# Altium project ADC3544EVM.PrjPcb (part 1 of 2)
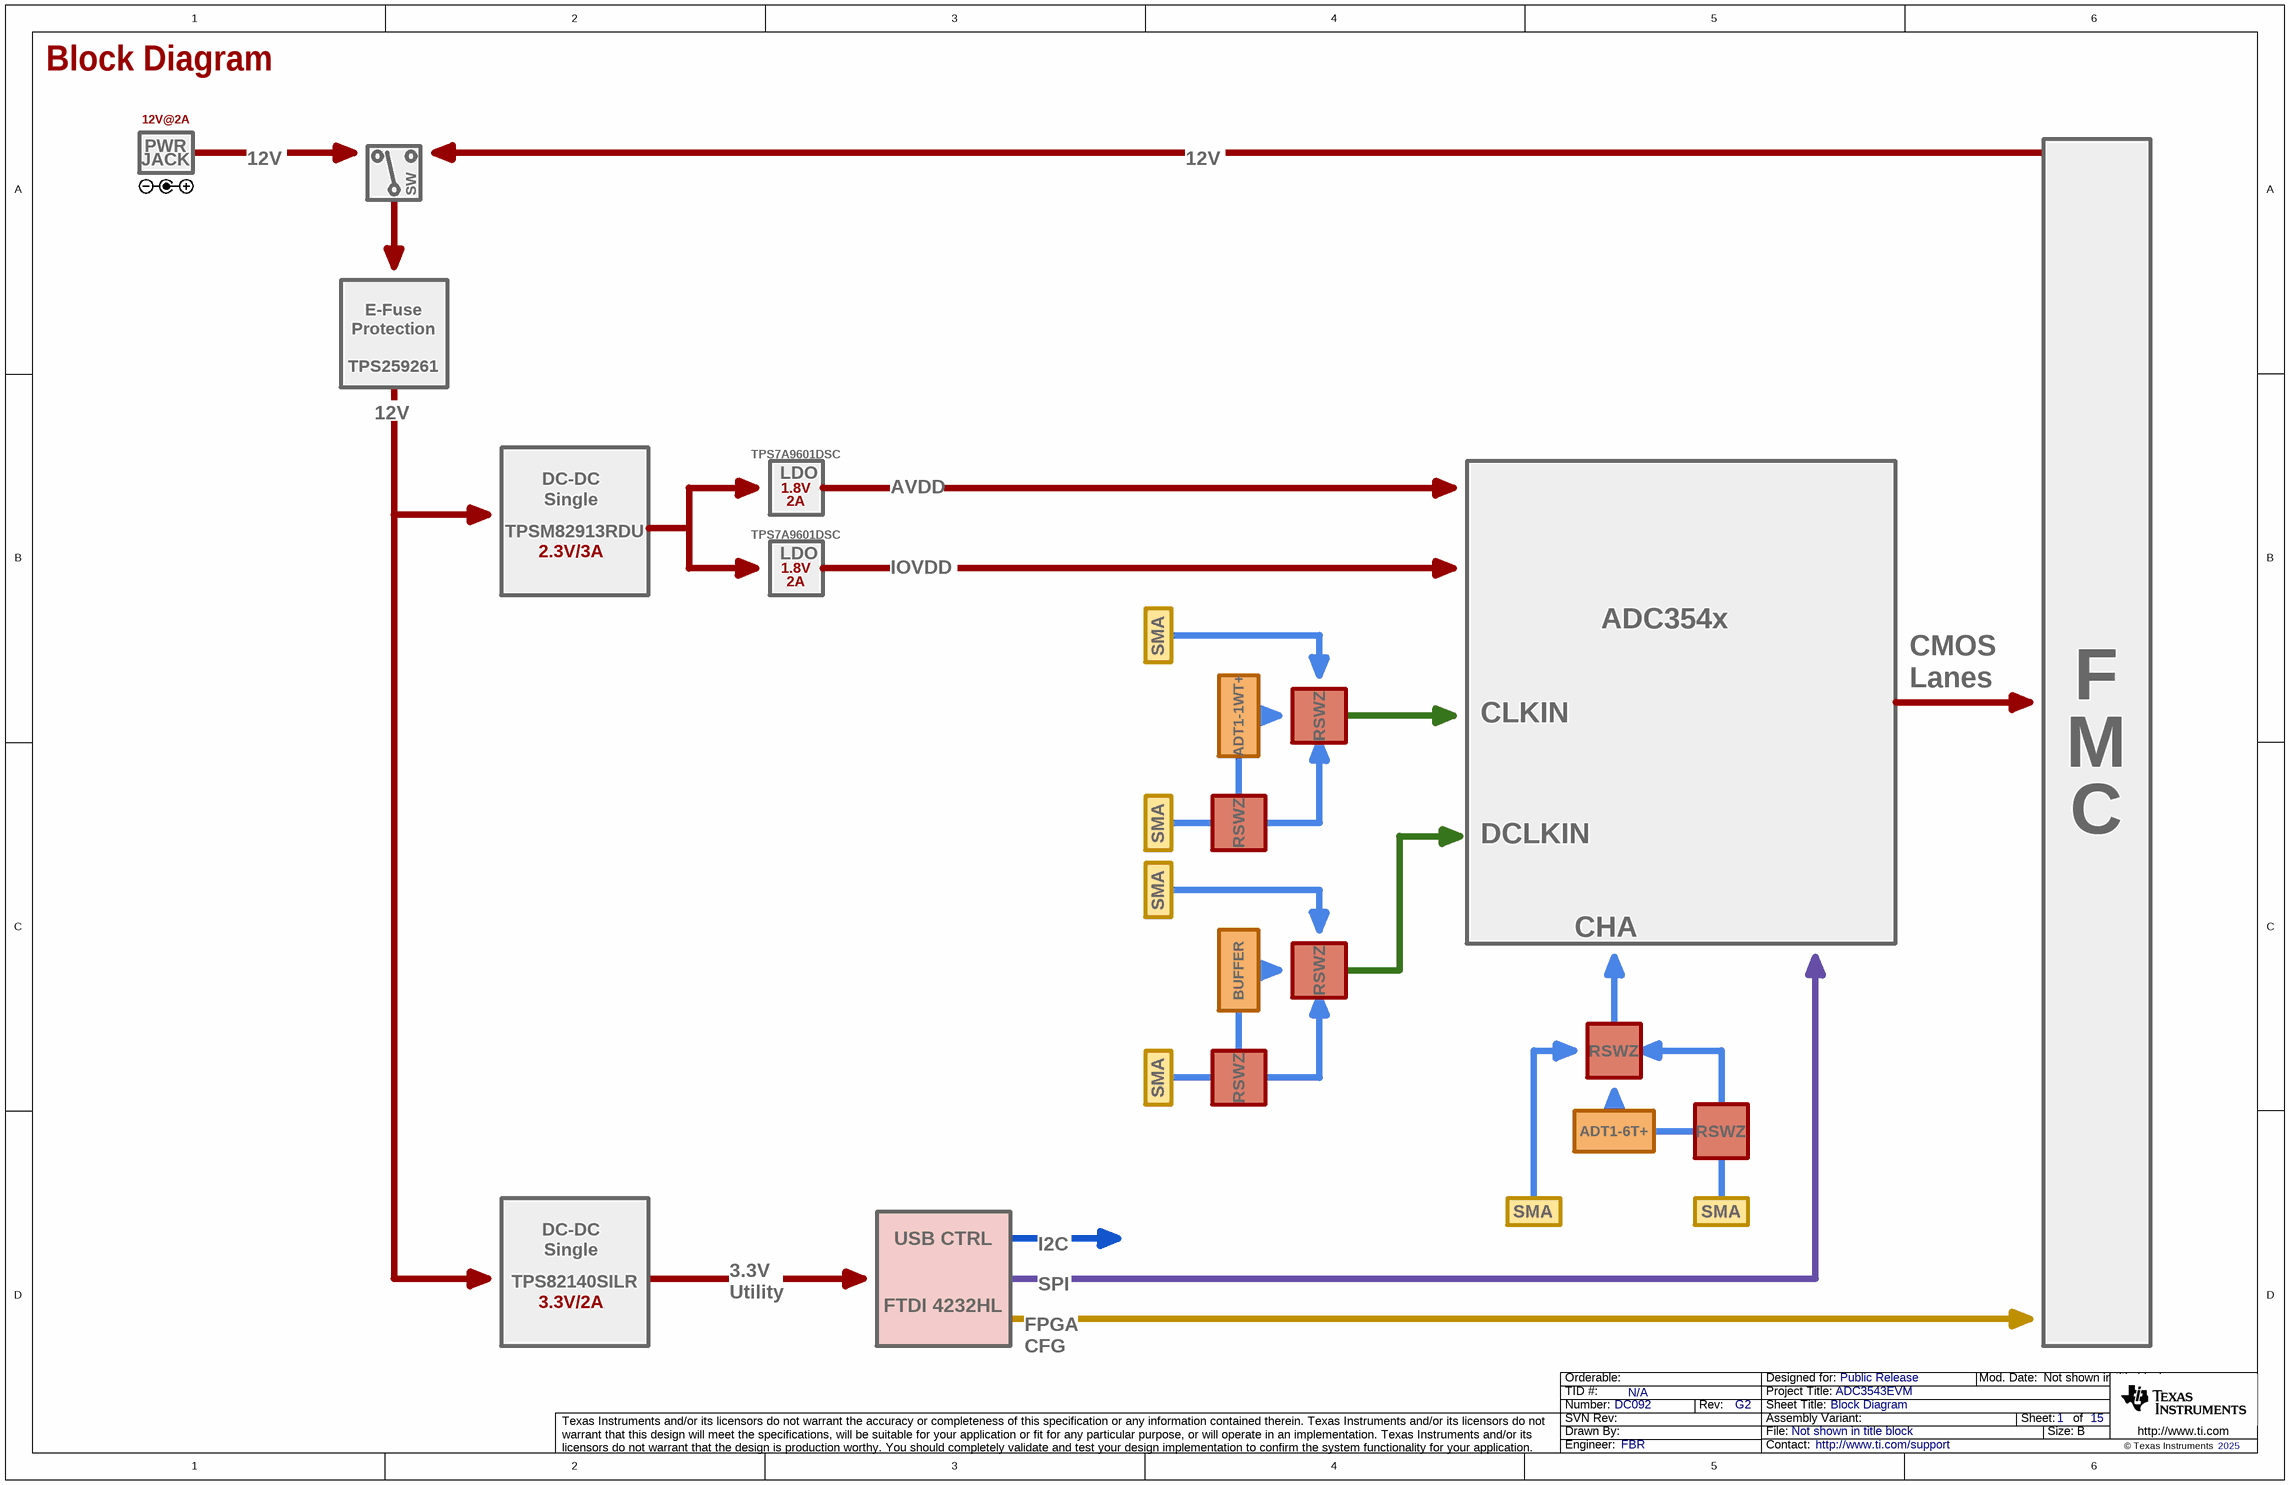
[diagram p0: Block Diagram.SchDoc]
CopyrightYear: 2025; PCB_Layout: GBR; PCB_Rev: G2; PRJ_Customer: Public Release; PRJ_Engineer: FBR; PRJ_Number: DC092; PRJ_Title: ADC3543EVM; SCH_Rev: G2; TechSupport: http://www.ti.com/support; TID: N/A
15 sheets, 386 parts. Net scope: flat (ports and power ports of the same name join across sheets).
Board file: ADC3543EVM.PcbDoc
Sheets:
  Block Diagram.SchDoc
  12V Input, Efuse and 3p3V Utility.SchDoc
  Power DC-DC.SchDoc
  Power LDO.SchDoc
  Power Sense ADC.SchDoc
  USB Control FTDI.SchDoc
  Comms LVL Shift and MUX.SchDoc
  CLK and DCLKIN.SchDoc
  ADC Inputs.SchDoc
  DUT IO.SchDoc
  FMC+ Sections A-E.SchDoc
  FMC+ Sections F-H, J, K.SchDoc
  Ouptut Buffer.SchDoc
  Hardware & Mechanicals.SchDoc
  Revision History.SchDoc

## Sheet Block Diagram.SchDoc: Block Diagram
size 431 x 279 mm; Date: Not shown in title block; ApprovedBy: Not shown in title block; CheckedBy: Not shown in title block; Author: Not shown in title block; CompanyName: Not shown in title block; Engineer: Not shown in title block; Organization: Not shown in title block; Address1: Not shown in title block; Address2: Not shown in title block; Address3: Not shown in title block; Address4: Not shown in title block; DocumentNumber: 1; Revision: Use project parameter SCH_Rev; SheetNumber: 1; SheetTotal: 15; PageSetup: Record=PageOptions¦CenterHorizontal=True¦CenterVertical=True¦PrintScale=1.00¦XCorrection=1.00¦YCorrection=1.00¦PrintKind=0¦BorderSize=5000000¦LeftOffset=0¦BottomOffset=0¦Orientation=2¦PaperLength=1000¦PaperWidth=1000¦Scale=100¦PaperSource=15¦PrintQuality=600¦MediaType=1¦DitherType=10¦PaperKind=Letter¦PrintScaleMode=1

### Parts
(Parts that share a designator on the sheet are numbered #1, #2 ... from top to bottom, then left to right.)
*#1  A_Value: 2A  V_Value: 1.8V  PartNum: TPS7A9601DSC  (hidden comment: LDO)  (graphical)
*#2  Limits: 2.3V/3A  PartNum: TPSM82913RDU  (hidden comment: DC-DC Single)  (graphical)
*#3  A_Value: 2A  V_Value: 1.8V  PartNum: TPS7A9601DSC  (hidden comment: LDO)  (graphical)
*#4  SMA  (graphical)
*#5  PartNum: ADT1-1WT+  (hidden comment: Balun)  (graphical)
*#6  PartNum: RSWZ  (hidden comment: R-SWIZZLE)  (graphical)
*#7  FMC  (value not drawn)  (graphical)
*#8  SMA  (graphical)
*#9  PartNum: RSWZ  (hidden comment: R-SWIZZLE)  (graphical)
*#10  SMA  (graphical)
*#11  PartNum: BUFFER  (hidden comment: Balun)  (graphical)
*#12  PartNum: RSWZ  (hidden comment: R-SWIZZLE)  (graphical)
*#13  PartNum: RSWZ  (hidden comment: R-SWIZZLE)  (graphical)
*#14  SMA  (graphical)
*#15  PartNum: RSWZ  (hidden comment: R-SWIZZLE)  (graphical)
*#16  PartNum: ADT1-6T+  (hidden comment: Balun)  (graphical)
*#17  PartNum: RSWZ  (hidden comment: R-SWIZZLE)  (graphical)
*#18  SMA  (graphical)
*#19  SMA  (graphical)
*#20  Limits: 3.3V/2A  PartNum: TPS82140SILR  (hidden comment: DC-DC Single)  (graphical)
*#21  FTDI 4232HL  (value not drawn)  (graphical)
*?#1  PartNum: 12V@2A  (hidden comment: Power Jack)  (graphical)
*?#2  SWITCH  (value not drawn)  (graphical)
*?#3  E-Fuse  (value not drawn)  (graphical)

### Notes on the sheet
- 12V
- AVDD
- IOVDD
- ADC354x
- CLKIN
- CMOS Lanes
- DCLKIN
- CHA
- 3.3V
  Utility
- I2C
- SPI
- FPGA
  CFG

## Sheet 12V Input, Efuse and 3p3V Utility.SchDoc: 12V Input & 3.3V Utility
size 431 x 279 mm; Date: Not shown in title block; ApprovedBy: Not shown in title block; CheckedBy: Not shown in title block; Author: Not shown in title block; CompanyName: Not shown in title block; Engineer: Not shown in title block; Organization: Not shown in title block; Address1: Not shown in title block; Address2: Not shown in title block; Address3: Not shown in title block; Address4: Not shown in title block; DocumentNumber: 1; Revision: Use project parameter SCH_Rev; SheetNumber: 2; SheetTotal: 14; PageSetup: Record=PageOptions¦CenterHorizontal=True¦CenterVertical=True¦PrintScale=1.00¦XCorrection=1.00¦YCorrection=1.00¦PrintKind=0¦BorderSize=5000000¦LeftOffset=0¦BottomOffset=0¦Orientation=2¦PaperLength=1000¦PaperWidth=1000¦Scale=100¦PaperSource=15¦PrintQuality=600¦MediaType=1¦DitherType=10¦PaperKind=Letter¦PrintScaleMode=1
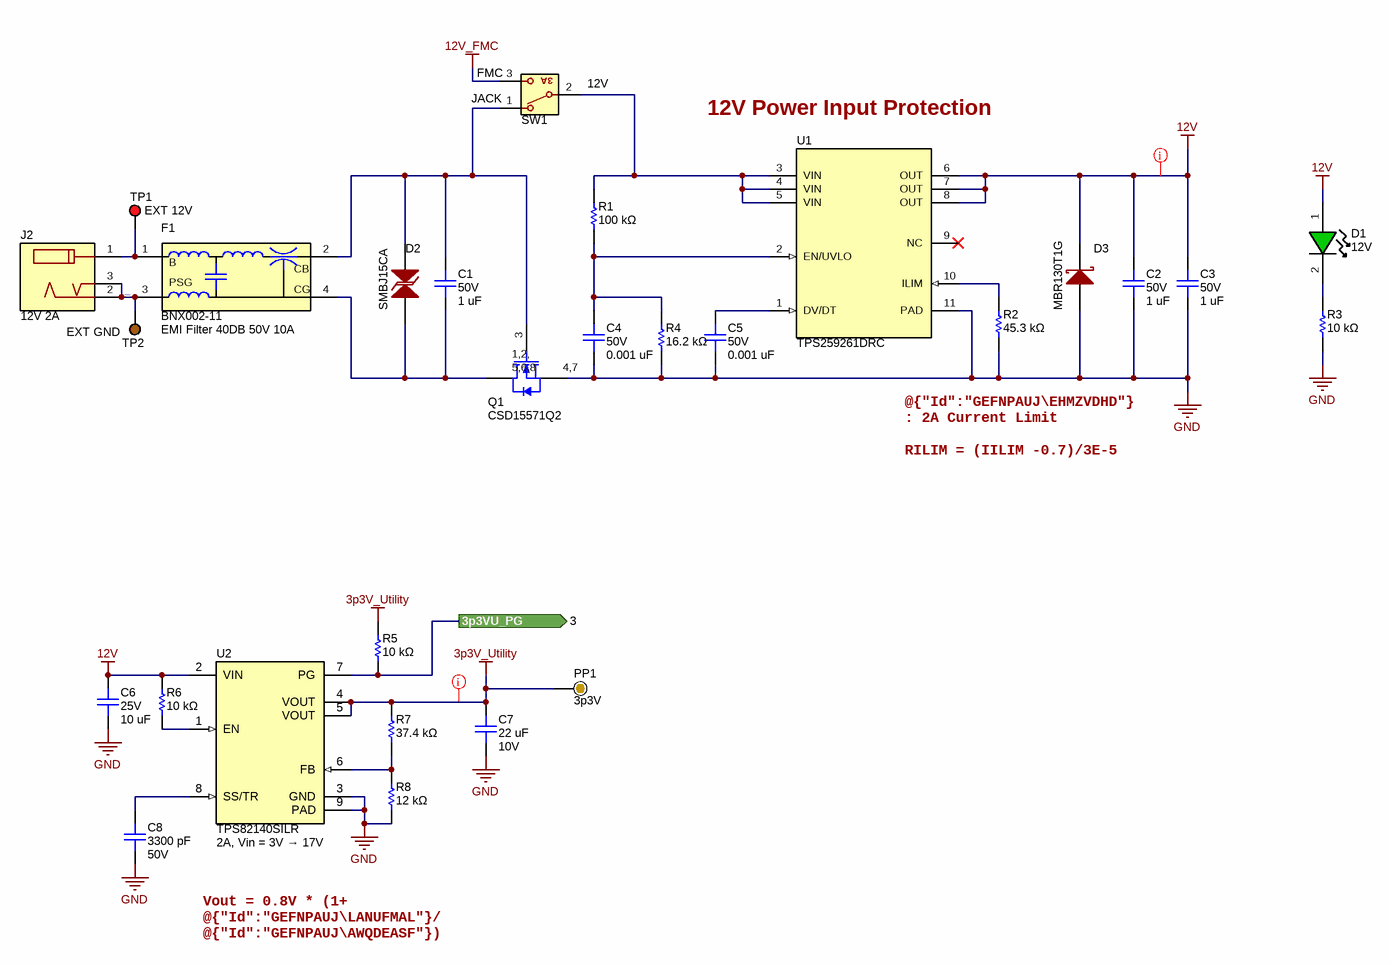
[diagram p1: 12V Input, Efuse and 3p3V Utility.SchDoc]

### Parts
C1  value 1 uF  Voltage - Rated: 50V  [0805L_cap]  (hidden comment: C2012X7R1H105K125AB)
C2  value 1 uF  Voltage - Rated: 50V  [0805L_cap]  (hidden comment: C2012X7R1H105K125AB)
C3  value 1 uF  Voltage - Rated: 50V  [0805L_cap]  (hidden comment: C2012X7R1H105K125AB)
C4  value 0.001 uF  Voltage - Rated: 50V  [0603L_cap]  (hidden comment: CGA3E2X7R1H102K080AA)
C5  value 0.001 uF  Voltage - Rated: 50V  [0603L_cap]  (hidden comment: CGA3E2X7R1H102K080AA)
C6  value 10 uF  Voltage - Rated: 25V  [0805L_cap]  (hidden comment: C2012X7S1E106K125AC)
C7  value 22 uF  Voltage - Rated: 10V  [0805L_cap]  (hidden comment: C2012X7S1A226M125AC)
C8  value 3300 pF  Voltage - Rated: 50V  [0402L_cap]  (hidden comment: CGA2B2X7R1H332K050BA)
D1  Text1: 12V  [LED_LTST-C190-Green]  (hidden comment: LTST-C191TGKT)
D2  SMBJ15CA  [SMBJ15CA]
D3  MBR130T1G  [SOD-123]
F1  BNX002-11  Text1: EMI Filter 40DB 50V 10A  [FIL_BNX002-11]
J2  Text1: 12V 2A  [RAPC722X]  (hidden comment: RAPC722X)
PP1  Text1: 3p3V  [ProbePoint_TH_40mil]  (hidden comment: Probe Point)  (no BOM)
Q1  CSD15571Q2  [DQK0006C]
R1  value 100 kΩ  [0402L]  (hidden comment: ERA-2AED104X)
R2  value 45.3 kΩ  [0402L]  (hidden comment: ERJ-2RKF4532X)
R3  value 10 kΩ  [0805L]  (hidden comment: ERJ-HP6F1002V)
R4  value 16.2 kΩ  [0402L]  (hidden comment: ERA-2AEB1622X)
R5  value 10 kΩ  [0402L]  (hidden comment: ERA-2AEB103X)
R6  value 10 kΩ  [0402L]  (hidden comment: ERA-2AEB103X)
R7  value 37.4 kΩ  [0402L]  (hidden comment: ERA-2AEB3742X)
R8  value 12 kΩ  [0402L]  (hidden comment: ERJ-2RKF1202X)
SW1  Text1: JACK  Text2: 12V  Text3: FMC  [500ASSP1M2QE]  (hidden comment: 500ASSP1M2QE)
TP1  Text1: EXT 12V  [Keystone5010]  (hidden comment: 5010)
TP2  Text1: EXT GND  [Keystone5125]  (hidden comment: 5125)
U1  TPS259261DRC  [DRC0010J]
U2  TPS82140SILR  Text1: 2A, Vin = 3V → 17V  [SIL0008D]

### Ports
3p3VU_PG (out, see 3)

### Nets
3p3V_Utility: C7.2 PP1.1 R5.2 R7.2 U2.4(VOUT) U2.5(VOUT)
12V: C2.2 C3.2 C6.2 D1.1(A) D3.1(K) R6.2 U1.6(OUT) U1.7(OUT) U1.8(OUT) U2.2(VIN)
12V_FMC: SW1.3
GND: C2.1 C3.1 C4.1 C5.1 C6.1 C7.1 C8.1 D3.2(A) Q1.4,7(S) R2.1 R3.1 R4.1 R8.1 U1.11(PAD) U2.3(GND) U2.9(PAD)
3p3VU_PG: R5.1 U2.7(PG) ; port 3p3VU_PG
EXTGND: F1.3(PSG) J2.2 J2.3 TP2.1
NetC1_1: C1.1 D2.2 F1.2(CB) Q1.3(G) SW1.1
NetC1_2: C1.2 D2.1 F1.4(CG) Q1.1,2,5,6,8(D)
NetC4_2: C4.2 R1.1 R4.2 U1.2(EN/UVLO)
NetC5_2: C5.2 U1.1(DV/DT)
NetC8_2: C8.2 U2.8(SS/TR)
NetD1_2: D1.2(K) R3.2
NetF1_1: F1.1(B) J2.1 TP1.1
NetR1_2: R1.2 SW1.2(COMM) U1.3(VIN) U1.4(VIN) U1.5(VIN)
NetR2_2: R2.2 U1.10(ILIM)
NetR6_1: R6.1 U2.1(EN)
NetR7_1: R7.1 R8.2 U2.6(FB)

Not connected (* = marked no-connect by the designer): U1 9(NC)*

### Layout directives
net class Power; net class GenPwr: 3p3V_Utility, 12V

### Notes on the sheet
- 12V Power Input Protection
- @{"Id":"GEFNPAUJ\EHMZVDHD"} : 2A Current Limit
  RILIM = (IILIM -0.7)/3E-5
- Vout = 0.8V * (1+ @{"Id":"GEFNPAUJ\LANUFMAL"}/ @{"Id":"GEFNPAUJ\AWQDEASF"})
  Vout = 3.3V

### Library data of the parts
C1-C3 = capcc02687: CAP CER 1UF 50V X7R 0805; Manufacturer: TDK Corporation; CompType: Capacitor Ceramic; Tolerance: ±10%; SizeX_mm: 2; SizeY_mm: 1.25; SizeZ_mm: 1.45
C4 C5 = capcc03751: CAP CER 1000PF 50V X7R 0603; Manufacturer: TDK Corporation; CompType: Capacitor Ceramic; Tolerance: ±10%; SizeX_mm: 1.6; SizeY_mm: 0.8; SizeZ_mm: 0.9
C6 = capcc03511: CAP CER 10UF 25V X7S 0805; Manufacturer: TDK Corporation; CompType: Capacitor Ceramic; Tolerance: ±10%; SizeX_mm: 2; SizeY_mm: 1.25; SizeZ_mm: 1.5
C7 = capcc09395: CAP CER 22UF 10V X7S 0805; Manufacturer: TDK Corporation; CompType: Capacitor Ceramic; Tolerance: ±20%; SizeX_mm: 2; SizeY_mm: 1.25; SizeZ_mm: 1.45
C8 = capcc04738: CAP CER 3300PF 50V X7R 0402; Manufacturer: TDK Corporation; CompType: Capacitor Ceramic; Tolerance: ±10%; SizeX_mm: 1; SizeY_mm: 0.5; SizeZ_mm: 0.55
D1 = cmp00247: LED GREEN CLEAR CHIP SMD; Manufacturer: Lite-On Inc.; Current Rating (Amps): 20mA; Voltage - Forward (Vf) (Typ): 3.2V; SizeX_mm: 1.6; SizeY_mm: 0.8; SizeZ_mm: 0.65
D2 = cmp00440: 24.4V Clamp 24.6A Ipp Tvs Diode; Manufacturer: Littlefuse; CompType: Diode TVS
D3 = cmp00438: DIODE SCHOTTKY 30V 1A SOD123; Manufacturer: Onsemi; Alt PartNumber: RB160M-30TR; Alt Manufacturer: Rohm Semiconductor
F1 = cmp00325: EMI Filter Circuits 40 DB 50V 10A; Manufacturer: Murata Electronics
J2 = cmp00022: Power Jack, mini, 2.1mm OD, R/A, TH; Manufacturer: Switchcraft
PP1 = Probe Point: Probe Point that can be used in lue of a test point; UniqueID: cmp00025
Q1 = cmp00159: MOSFET, N-CH, 20 V, 10 A; Manufacturer: Texas Instruments; CompType: FET
R1 = RSMD040200361: RES SMD 100K OHM 0.5% 1/16W 0402; Manufacturer: Panasonic Electronic Components; CompType: Resistor SMD; Power (Watts): 0.063W, 1/16W; Temperature Coefficient: ±25ppm/°C; SizeX_mm: 1; SizeY_mm: 0.5; SizeZ_mm: 0.4
R2 = RSMD040202774: RES SMD 45.3K OHM 1% 1/10W 0402; Manufacturer: Panasonic Electronic Components; CompType: Resistor SMD; Power (Watts): 0.1W, 1/10W; Temperature Coefficient: ±100ppm/°C; SizeX_mm: 1; SizeY_mm: 0.5; SizeZ_mm: 0.4
R3 = RSMD080502076: RES 10K OHM 1% 1/2W 0805; Manufacturer: Panasonic Electronic Components; CompType: Resistor SMD; Power (Watts): 0.5W, 1/2W; Temperature Coefficient: ±100ppm/°C; SizeX_mm: 2; SizeY_mm: 1.25; SizeZ_mm: 0.7
R4 = RSMD040200899: RES SMD 16.2KOHM 0.1% 1/16W 0402; Manufacturer: Panasonic Electronic Components; CompType: Resistor SMD; Power (Watts): 0.063W, 1/16W; Temperature Coefficient: ±25ppm/°C; SizeX_mm: 1; SizeY_mm: 0.5; SizeZ_mm: 0.4
R5 R6 = RSMD040200315: RES SMD 10K OHM 0.1% 1/16W 0402; Manufacturer: Panasonic Electronic Components; CompType: Resistor SMD; Power (Watts): 0.063W, 1/16W; Temperature Coefficient: ±25ppm/°C; SizeX_mm: 1; SizeY_mm: 0.5; SizeZ_mm: 0.4
R7 = RSMD040202418: RES SMD 37.4KOHM 0.1% 1/16W 0402; Manufacturer: Panasonic Electronic Components; CompType: Resistor SMD; Power (Watts): 0.063W, 1/16W; Temperature Coefficient: ±25ppm/°C; SizeX_mm: 1; SizeY_mm: 0.5; SizeZ_mm: 0.4
R8 = RSMD040200519: RES SMD 12K OHM 1% 1/10W 0402; Manufacturer: Panasonic Electronic Components; CompType: Resistor SMD; Power (Watts): 0.1W, 1/10W; Temperature Coefficient: ±100ppm/°C; SizeX_mm: 1; SizeY_mm: 0.5; SizeZ_mm: 0.4
SW1 = cmp00460: SWITCH SLIDE SPDT 3A 120V; Manufacturer: E-Switch; Pitch (mm): 2.54
TP1 = cmp00040: Test Point, Multipurpose, Red, TH; Manufacturer: Keystone
TP2 = cmp00047: Test Point, Multipurpose, Brown, TH; Manufacturer: Keystone
U1 = cmp00157: 12V, 5A, 30mΩ eFuse with Adjustable +/-15% Accurate Current Limit, DRC0010J (VSON-10); Manufacturer: Texas Instruments
U2 = TPS82140SILR: 17V Input 2A Synchronous Step-Down Converter MicroSiP Module With Integrated Inductor, SIL0008D (uSIP-8); Manufacturer: Texas Instruments; Alternate PartNumber: TPS82140SILT; CompType: Switcher

## Sheet Power DC-DC.SchDoc: DC/DC regulator
size 431 x 279 mm; Date: Not shown in title block; ApprovedBy: Not shown in title block; CheckedBy: Not shown in title block; Author: Not shown in title block; CompanyName: Not shown in title block; Engineer: Not shown in title block; Organization: Not shown in title block; Address1: Not shown in title block; Address2: Not shown in title block; Address3: Not shown in title block; Address4: Not shown in title block; DocumentNumber: 1; Revision: Use project parameter SCH_Rev; SheetNumber: 3; SheetTotal: 14; PageSetup: Record=PageOptions¦CenterHorizontal=True¦CenterVertical=True¦PrintScale=1.00¦XCorrection=1.00¦YCorrection=1.00¦PrintKind=0¦BorderSize=5000000¦LeftOffset=0¦BottomOffset=0¦Orientation=2¦PaperLength=1000¦PaperWidth=1000¦Scale=100¦PaperSource=15¦PrintQuality=600¦MediaType=1¦DitherType=10¦PaperKind=Letter¦PrintScaleMode=1
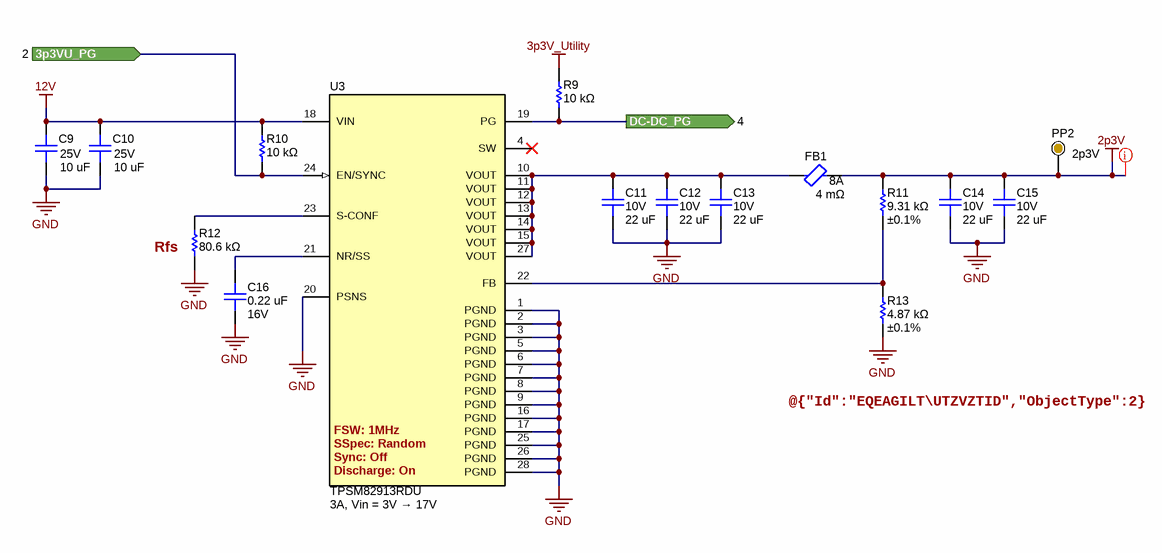
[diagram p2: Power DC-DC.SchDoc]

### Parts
C9  value 10 uF  Voltage - Rated: 25V  [0805L_cap]  (hidden comment: C2012X7S1E106K125AC)
C10  value 10 uF  Voltage - Rated: 25V  [0805L_cap]  (hidden comment: C2012X7S1E106K125AC)
C11  value 22 uF  Voltage - Rated: 10V  [0805L_cap]  (hidden comment: C2012X7S1A226M125AC)
C12  value 22 uF  Voltage - Rated: 10V  [0805L_cap]  (hidden comment: C2012X7S1A226M125AC)
C13  value 22 uF  Voltage - Rated: 10V  [0805L_cap]  (hidden comment: C2012X7S1A226M125AC)
C14  value 22 uF  Voltage - Rated: 10V  [0805L_cap]  (hidden comment: C2012X7S1A226M125AC)
C15  value 22 uF  Voltage - Rated: 10V  [0805L_cap]  (hidden comment: C2012X7S1A226M125AC)
C16  value 0.22 uF  Voltage - Rated: 16V  [0402L_cap]  (hidden comment: CGA2B1X5R1C224M050BC)
FB1  DCR: 4 mΩ  Current: 8A  [0603L]  (hidden comment: BLE18PS080SN1D)
PP2  Text1: 2p3V  [ProbePoint_TH_40mil]  (hidden comment: Probe Point)  (no BOM)
R9  value 10 kΩ  [0402L]  (hidden comment: ERA-2AEB103X)
R10  value 10 kΩ  [0402L]  (hidden comment: ERA-2AEB103X)
R11  value 9.31 kΩ  Tolerance: ±0.1%  [0402L]  (hidden comment: ERA-2AEB9311X)
R12  value 80.6 kΩ  [0402L]  (hidden comment: ERJ-2RKF8062X)
R13  value 4.87 kΩ  Tolerance: ±0.1%  [0402L]  (hidden comment: ERA-2AEB4871X)
U3  TPSM82913RDU  Text1: 3A, Vin = 3V → 17V  Discharge: On  Sync: Off  SSpec: Random  FSW: 1MHz  [RDU0028A]

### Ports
3p3VU_PG (in, see 2), DC-DC_PG (out, see 4)

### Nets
2p3V: C14.2 C15.2 FB1.2 PP2.1 R11.2
3p3V_Utility: R9.2
12V: C9.2 C10.2 R10.2 U3.18(VIN)
GND: C9.1 C10.1 C11.1 C12.1 C13.1 C14.1 C15.1 C16.2 R12.1 R13.1 U3.1(PGND) U3.2(PGND) U3.3(PGND) U3.5(PGND) U3.6(PGND) U3.7(PGND) U3.8(PGND) U3.9(PGND) U3.16(PGND) U3.17(PGND) U3.20(PSNS) U3.25(PGND) U3.26(PGND) U3.28(PGND)
3p3VU_PG: R10.1 U3.24(EN/SYNC) ; port 3p3VU_PG
DC-DC_PG: R9.1 U3.19(PG) ; port DC-DC_PG
NetC11_2: C11.2 C12.2 C13.2 FB1.1 U3.10(VOUT) U3.11(VOUT) U3.12(VOUT) U3.13(VOUT) U3.14(VOUT) U3.15(VOUT) U3.27(VOUT)
NetC16_1: C16.1 U3.21(NR/SS)
NetR11_1: R11.1 R13.2 U3.22(FB)
NetR12_2: R12.2 U3.23(S-CONF)

Not connected (* = marked no-connect by the designer): U3 4(SW)*

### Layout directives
net class Power; net class GenPwr: 2p3V

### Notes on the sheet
- (near R12) Rfs
- @{"Id":"EQEAGILT\UTZVZTID","ObjectType":2} = @{"Id":"EQEAGILT\NLLUWDBR","ObjectType":2} *(VOUT/0.8 -1)

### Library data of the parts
C9 C10 = capcc03511: as C6 on sheet 12V Input, Efuse and 3p3V Utility
C11-C15 = capcc09395: as C7 on sheet 12V Input, Efuse and 3p3V Utility
C16 = capcc01693: CAP CER 0.22UF 16V X5R 0402; Manufacturer: TDK Corporation; CompType: Capacitor Ceramic; Tolerance: ±20%; SizeX_mm: 1; SizeY_mm: 0.5; SizeZ_mm: 0.55
FB1 = dcp00004: 8.5 Ohms @ 100 MHz 1 Power Line Ferrite Bead 0603 (1608 Metric) 8A 4mOhm; Manufacturer: Murata; Impedance: 8.5 Ω; SizeX_mm: 1.6; SizeY_mm: 0.8
PP2 = cmp00025: Probe Point that can be used in lue of a test point
R9 R10 = RSMD040200315: as R5 on sheet 12V Input, Efuse and 3p3V Utility
R11 = RSMD040203923: RES SMD 9.31KOHM 0.1% 1/16W 0402; Manufacturer: Panasonic Electronic Components; CompType: Resistor SMD; Power (Watts): 0.063W, 1/16W; Temperature Coefficient: ±25ppm/°C; SizeX_mm: 1; SizeY_mm: 0.5; SizeZ_mm: 0.4
R12 = RSMD040203748: RES SMD 80.6K OHM 1% 1/10W 0402; Manufacturer: Panasonic Electronic Components; CompType: Resistor SMD; Power (Watts): 0.1W, 1/10W; Temperature Coefficient: ±100ppm/°C; SizeX_mm: 1; SizeY_mm: 0.5; SizeZ_mm: 0.4
R13 = RSMD040202615: RES SMD 4.87KOHM 0.1% 1/16W 0402; Manufacturer: Panasonic Electronic Components; CompType: Resistor SMD; Power (Watts): 0.063W, 1/16W; Temperature Coefficient: ±25ppm/°C; SizeX_mm: 1; SizeY_mm: 0.5; SizeZ_mm: 0.4
U3 = cmp00201: 3-V to 17-V, 3-A Low-Noise and Low-Ripple Buck Power Module with Integrated Ferrite Bead Filter Compensation; Part Number: TPSM82913RDUR; Manufacturer: Texas Instruments; Switching Frequency: 1/2.2MHz; Max Duty Cycle: 100%; Output Voltage: 0.8-5.5V; Standoff Height: 0mm; CompType: Switcher; Number Of Outputs: 1; Max Supply Voltage: 17V; AEC Category: Q200; TJmax_C: +125°C; Nominal Supply Current: 5mA; Output Type: AdjustableProgrammable; Min Supply Voltage: 3V; AEC Qualified: No

## Sheet Power LDO.SchDoc: LDOs
size 431 x 279 mm; Date: Not shown in title block; ApprovedBy: Not shown in title block; CheckedBy: Not shown in title block; Author: Not shown in title block; CompanyName: Not shown in title block; Engineer: Not shown in title block; Organization: Not shown in title block; Address1: Not shown in title block; Address2: Not shown in title block; Address3: Not shown in title block; Address4: Not shown in title block; DocumentNumber: 1; Revision: Use project parameter SCH_Rev; SheetNumber: 4; SheetTotal: 14; PageSetup: Record=PageOptions¦CenterHorizontal=True¦CenterVertical=True¦PrintScale=1.00¦XCorrection=1.00¦YCorrection=1.00¦PrintKind=0¦BorderSize=5000000¦LeftOffset=0¦BottomOffset=0¦Orientation=2¦PaperLength=1000¦PaperWidth=1000¦Scale=100¦PaperSource=15¦PrintQuality=600¦MediaType=1¦DitherType=10¦PaperKind=Letter¦PrintScaleMode=1
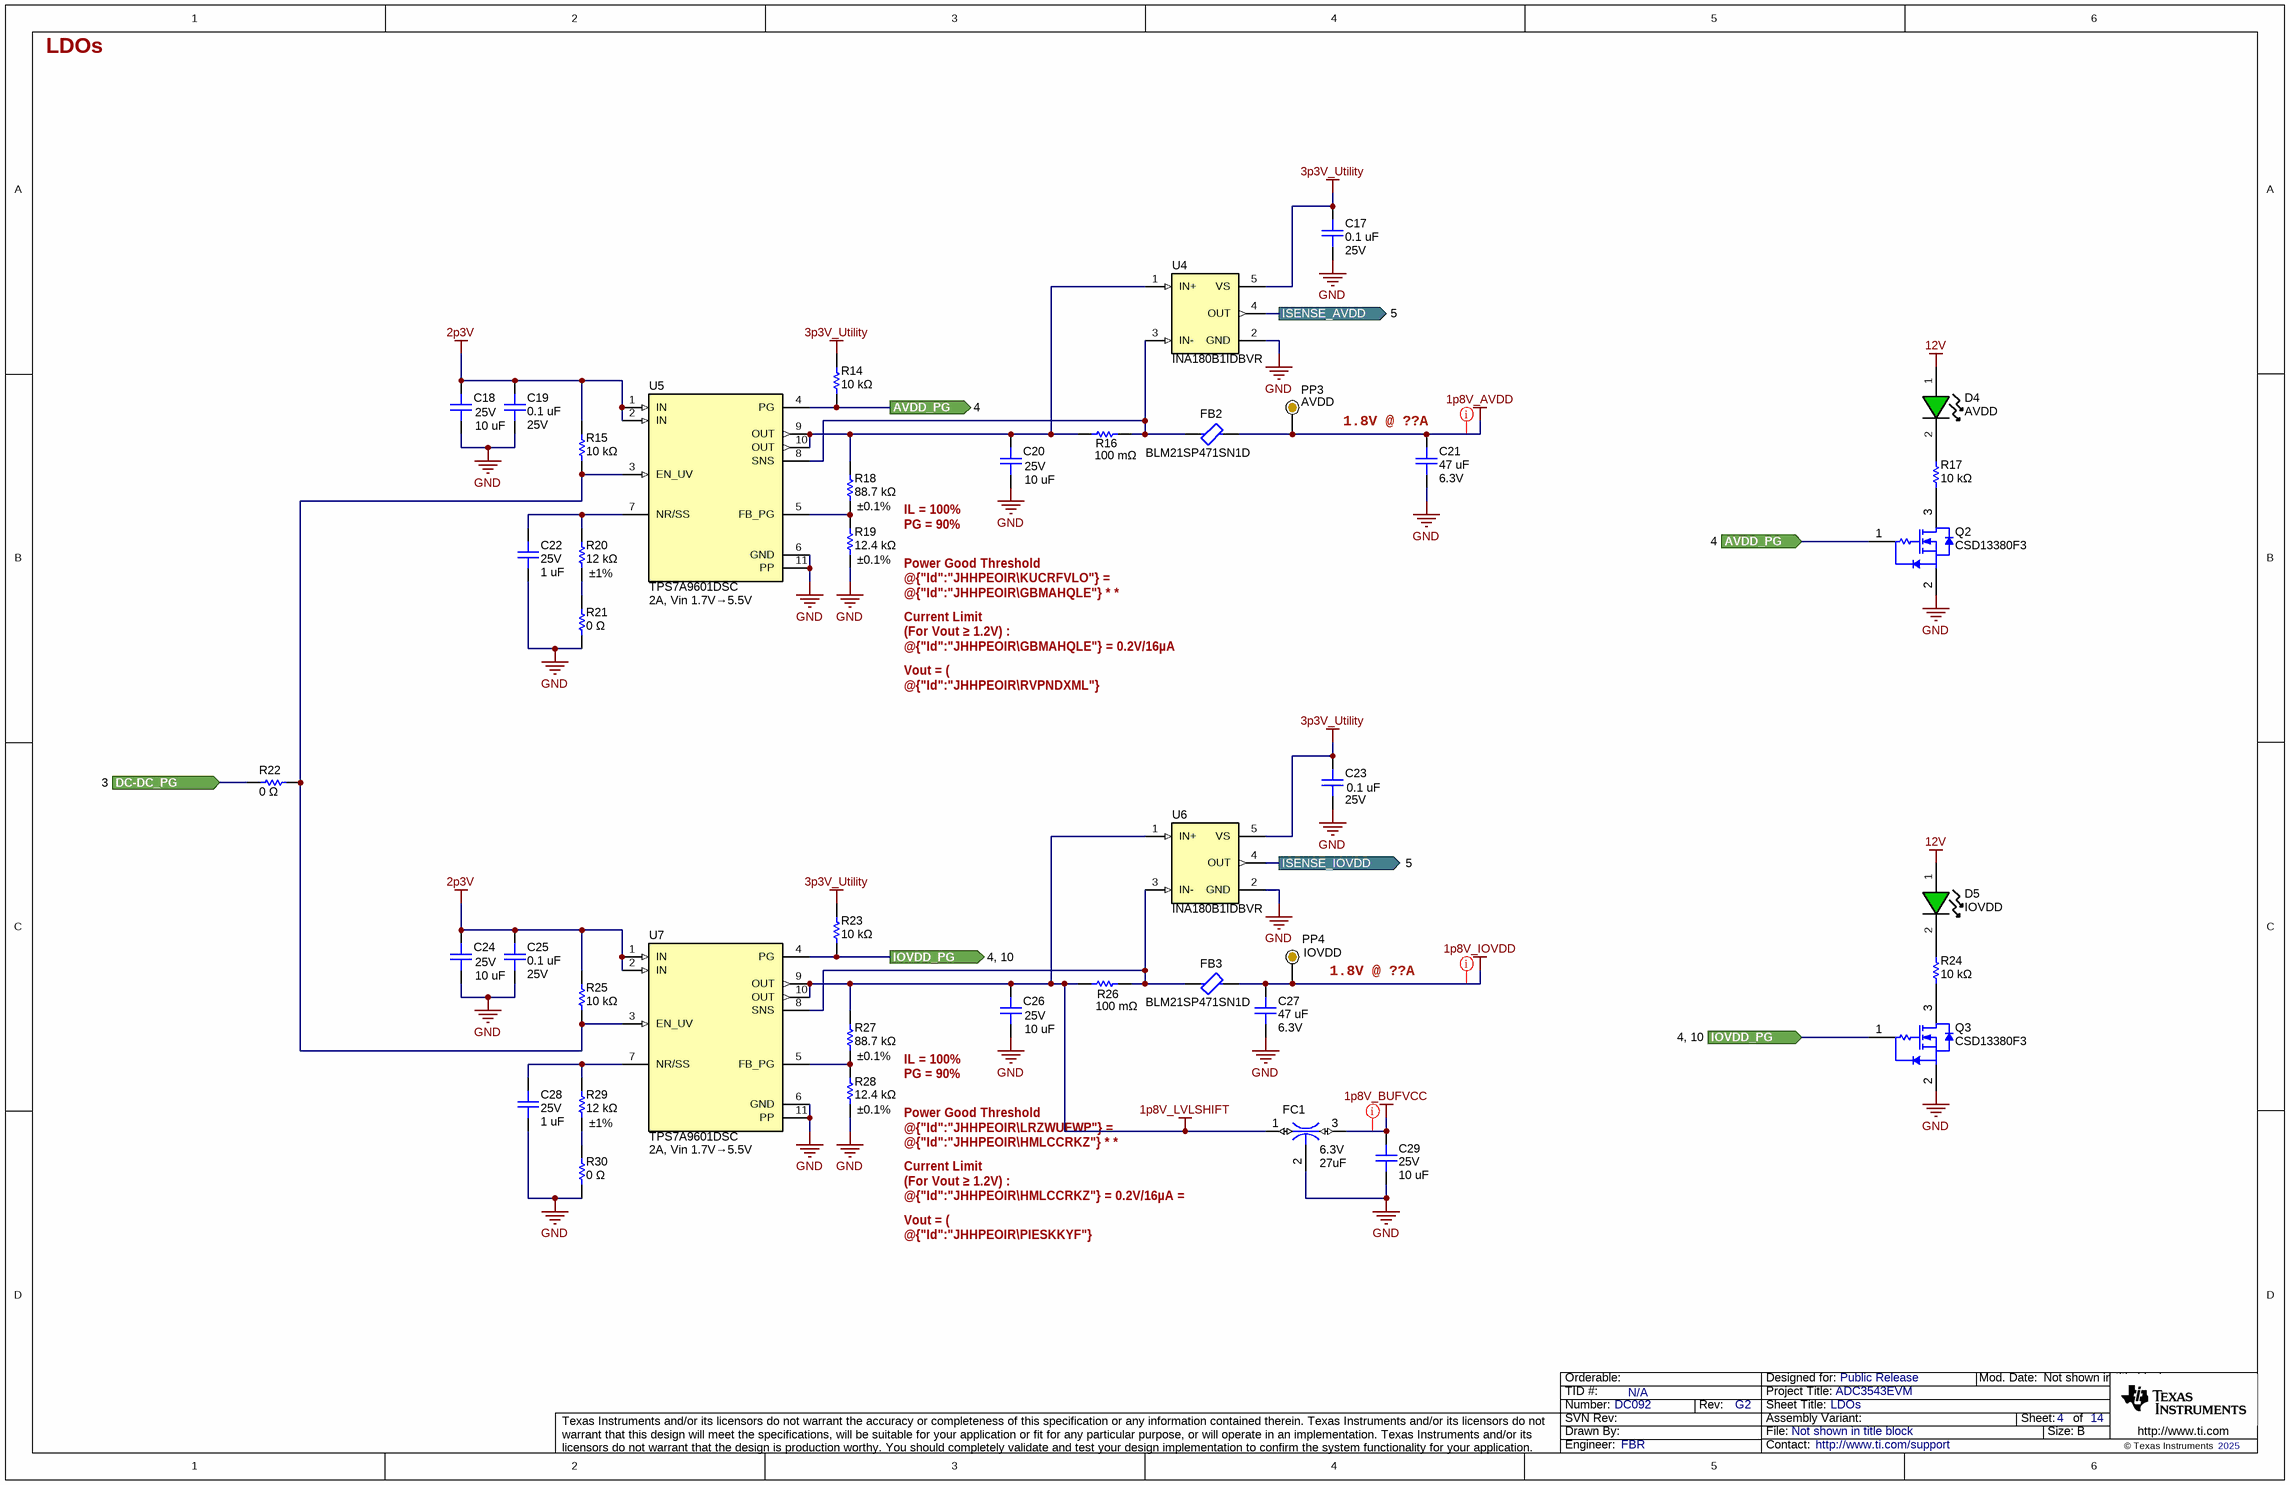
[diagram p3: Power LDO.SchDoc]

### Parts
C17  value 0.1 uF  Voltage - Rated: 25V  [0402L_cap]  (hidden comment: GRT155R71E104KE01J)
C18  value 10 uF  Voltage - Rated: 25V  [0805L_cap]  (hidden comment: C2012X7S1E106K125AC)
C19  value 0.1 uF  Voltage - Rated: 25V  [0402L_cap]  (hidden comment: GRT155R71E104KE01J)
C20  value 10 uF  Voltage - Rated: 25V  [0805L_cap]  (hidden comment: C2012X7S1E106K125AC)
C21  value 47 uF  Voltage - Rated: 6.3V  [0603L_cap]  (hidden comment: GRM188R60J476ME15D)
C22  value 1 uF  Voltage - Rated: 25V  [0402L_cap]  (hidden comment: C1005X5R1E105K050BC)
C23  value 0.1 uF  Voltage - Rated: 25V  [0402L_cap]  (hidden comment: GRT155R71E104KE01J)
C24  value 10 uF  Voltage - Rated: 25V  [0805L_cap]  (hidden comment: C2012X7S1E106K125AC)
C25  value 0.1 uF  Voltage - Rated: 25V  [0402L_cap]  (hidden comment: GRT155R71E104KE01J)
C26  value 10 uF  Voltage - Rated: 25V  [0805L_cap]  (hidden comment: C2012X7S1E106K125AC)
C27  value 47 uF  Voltage - Rated: 6.3V  [0603L_cap]  (hidden comment: GRM188R60J476ME15D)
C28  value 1 uF  Voltage - Rated: 25V  [0402L_cap]  (hidden comment: C1005X5R1E105K050BC)
C29  value 10 uF  Voltage - Rated: 25V  [0603L_cap]  (hidden comment: GRM188R61E106KA73J)
D4  Text1: AVDD  [LED_LTST-C190-Green]  (hidden comment: LTST-C191TGKT)
D5  Text1: IOVDD  [LED_LTST-C190-Green]  (hidden comment: LTST-C191TGKT)
FB2  BLM21SP471SN1D  [0805L]
FB3  BLM21SP471SN1D  [0805L]
FC1  value 27uF  Voltage - Rated: 6.3V  [NFM31PC]  (hidden comment: dcp00001)
PP3  Text1: AVDD  [ProbePoint_TH_40mil]  (hidden comment: Probe Point)  (no BOM)
PP4  Text1: IOVDD  [ProbePoint_TH_40mil]  (hidden comment: Probe Point)  (no BOM)
Q2  CSD13380F3  [YJM0003A]
Q3  CSD13380F3  [YJM0003A]
R14  value 10 kΩ  [0402L]  (hidden comment: ERA-2AEB103X)
R15  value 10 kΩ  [0402L]  (hidden comment: ERA-2AEB103X)
R16  value 100 mΩ  [CCS0603FLxLxx]  (hidden comment: WSLP0603R1000FEA)
R17  value 10 kΩ  [0805L]  (hidden comment: ERJ-HP6F1002V)
R18  value 88.7 kΩ  Tolerance: ±0.1%  [0402L]  (hidden comment: RT0402BRD0788K7L)
R19  value 12.4 kΩ  Tolerance: ±0.1%  [0402L]  (hidden comment: ERA-2AEB1242X)
R20  value 12 kΩ  Tolerance: ±1%  [0402L]  (hidden comment: ERJ-2RKF1202X)
R21  value 0 Ω  [0402L]  (hidden comment: ERJ-U020R00X)
R22  value 0 Ω  [0402L]  (hidden comment: ERJ-U020R00X)
R23  value 10 kΩ  [0402L]  (hidden comment: ERA-2AEB103X)
R24  value 10 kΩ  [0805L]  (hidden comment: ERJ-HP6F1002V)
R25  value 10 kΩ  [0402L]  (hidden comment: ERA-2AEB103X)
R26  value 100 mΩ  [CCS0603FLxLxx]  (hidden comment: WSLP0603R1000FEA)
R27  value 88.7 kΩ  Tolerance: ±0.1%  [0402L]  (hidden comment: RT0402BRD0788K7L)
R28  value 12.4 kΩ  Tolerance: ±0.1%  [0402L]  (hidden comment: ERA-2AEB1242X)
R29  value 12 kΩ  Tolerance: ±1%  [0402L]  (hidden comment: ERJ-2RKF1202X)
R30  value 0 Ω  [0402L]  (hidden comment: ERJ-U020R00X)
U4  INA180B1IDBVR  [DBV0005A]
U5  TPS7A9601DSC  Text1: 2A, Vin 1.7V→5.5V  [DRC0010J]
U6  INA180B1IDBVR  [DBV0005A]
U7  TPS7A9601DSC  Text1: 2A, Vin 1.7V→5.5V  [DRC0010J]

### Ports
AVDD_PG (in, see 4), AVDD_PG (out, see 4), DC-DC_PG (in, see 3), IOVDD_PG (in, see 4, 10), IOVDD_PG (out, see 4, 10), ISENSE_AVDD (out, see 5), ISENSE_IOVDD (out, see 5)

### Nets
1p8V_AVDD: C21.2 FB2.2 PP3.1
1p8V_BUFVCC: C29.2 FC1.3
1p8V_IOVDD: C27.2 FB3.2 PP4.1
1p8V_LVLSHIFT: C26.2 FC1.1 R26.1 R27.2 U6.1(IN+) U7.9(OUT) U7.10(OUT)
2p3V: C18.2 C19.2 C24.2 C25.2 R15.2 R25.2 U5.1(IN) U5.2(IN) U7.1(IN) U7.2(IN)
3p3V_Utility: C17.2 C23.2 R14.2 R23.2 U4.5(VS) U6.5(VS)
12V: D4.1(A) D5.1(A)
GND: C17.1 C18.1 C19.1 C20.1 C21.1 C22.1 C23.1 C24.1 C25.1 C26.1 C27.1 C28.1 C29.1 FC1.2 Q2.2(S) Q3.2(S) R19.1 R21.1 R28.1 R30.1 U4.2(GND) U5.6(GND) U5.11(PP) U6.2(GND) U7.6(GND) U7.11(PP)
AVDD_PG: Q2.1(G) R14.1 U5.4(PG) ; port AVDD_PG
DC-DC_PG: R22.2 ; port DC-DC_PG
IOVDD_PG: Q3.1(G) R23.1 U7.4(PG) ; port IOVDD_PG
ISENSE_AVDD: U4.4(OUT) ; port ISENSE_AVDD
ISENSE_IOVDD: U6.4(OUT) ; port ISENSE_IOVDD
NetC20_2: C20.2 R16.1 R18.2 U4.1(IN+) U5.9(OUT) U5.10(OUT)
NetC22_2: C22.2 R20.2 U5.7(NR/SS)
NetC28_2: C28.2 R29.2 U7.7(NR/SS)
NetD4_2: D4.2(K) R17.2
NetD5_2: D5.2(K) R24.2
NetFB2_1: FB2.1 R16.2 U4.3(IN-) U5.8(SNS)
NetFB3_1: FB3.1 R26.2 U6.3(IN-) U7.8(SNS)
NetQ2_3: Q2.3(D) R17.1
NetQ3_3: Q3.3(D) R24.1
NetR15_1: R15.1 R22.1 R25.1 U5.3(EN_UV) U7.3(EN_UV)
NetR18_1: R18.1 R19.2 U5.5(FB_PG)
NetR20_1: R20.1 R21.2
NetR27_1: R27.1 R28.2 U7.5(FB_PG)
NetR29_1: R29.1 R30.2

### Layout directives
net class Power; net class DUTPwr: 1p8V_AVDD, 1p8V_BUFVCC, 1p8V_IOVDD

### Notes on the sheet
- (near C21) 1.8V @ ??A
- IL = 100%
  PG = 90%
- Power Good Threshold
  @{"Id":"JHHPEOIR\KUCRFVLO"} = @{"Id":"JHHPEOIR\GBMAHQLE"} * * (VOUT/0.2*K-1)
  K = PG % Threshold
- Current Limit
  (For Vout ≥ 1.2V) : @{"Id":"JHHPEOIR\GBMAHQLE"} = 0.2V/16µA = 12.4k
- Vout = ( @{"Id":"JHHPEOIR\RVPNDXML"} + @{"Id":"JHHPEOIR\VYCEATNQ"} ) *150µA
  Vout = 1.8V
- (near PP4) 1.8V @ ??A
- Power Good Threshold
  @{"Id":"JHHPEOIR\LRZWUFWP"} = @{"Id":"JHHPEOIR\HMLCCRKZ"} * * (VOUT/0.2*K-1)
  K = PG % Threshold
- Current Limit
  (For Vout ≥ 1.2V) : @{"Id":"JHHPEOIR\HMLCCRKZ"} = 0.2V/16µA = 12.4k
- Vout = ( @{"Id":"JHHPEOIR\PIESKKYF"} + @{"Id":"JHHPEOIR\BNWUTHKX"} ) *150µA
  Vout = 1.8V

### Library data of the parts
C17 C19 C23 C25 = capcc09401: CAP CER 0.1UF 25V X7R 0402; Manufacturer: Murata; CompType: Capacitor Ceramic; Tolerance: ±10%; SizeX_mm: 1; SizeY_mm: 0.5; SizeZ_mm: 0.7
C18 C20 C24 C26 = capcc03511: as C6 on sheet 12V Input, Efuse and 3p3V Utility
C21 C27 = GRM188R60J476ME15D: CAP CER 47UF 6.3V X5R 0603; Manufacturer: Murata; CompType: Capacitor Ceramic; Tolerance: ±20%; SizeX_mm: 1.6; SizeY_mm: 0.81; SizeZ_mm: 0.9
C22 C28 = capcc02750: CAP CER 1UF 25V X5R 0402; Manufacturer: TDK Corporation; CompType: Capacitor Ceramic; Tolerance: ±10%; SizeX_mm: 1; SizeY_mm: 0.5; SizeZ_mm: 0.55
C29 = capcc09400: CAP CER 10UF 25V X5R 0603; Manufacturer: Murata; CompType: Capacitor Ceramic; Tolerance: ±10%; SizeX_mm: 1.6; SizeY_mm: 0.8; SizeZ_mm: 1
D4 D5 = cmp00247: as D1 on sheet 12V Input, Efuse and 3p3V Utility
FB2 FB3 = dcp00579: FERRITEBEAD SMD Z100MHZ=470OHM 2; Manufacturer: Murata Electronics; Current: 2.5A; Impedance: 470 Ω
FC1 = dcp00001: Feed through capactior 27uF; PartNumber: NFM31PC276B0J3L; Manufacturer: Murata; CompType: Feed Thru Cap; Tolerance: ±20%; SizeX_mm: 3.2; SizeY_mm: 1.6; SizeZ_mm: 1.5; Current: 6A; DCR: 5 mΩ
PP3 PP4 = Probe Point: as PP1 on sheet 12V Input, Efuse and 3p3V Utility
Q2 Q3 = CSD13380F3: MOSFET, N-CH, 12 V, 3.6 A, YJM0003A (PICOSTAR-3); Manufacturer: Texas Instruments; CompType: NMOS
R14 R15 R23 R25 = RSMD040200315: as R5 on sheet 12V Input, Efuse and 3p3V Utility
R16 R26 = WSLP0603R1000FEA: RES 0.1 OHM 1% 2/5W 0603; Manufacturer: Vishay Dale; CompType: Resistor SMD Sense; Resistance: 3 mΩ; Power (Watts): 0.4W, 2/5W
R17 R24 = RSMD080502076: as R3 on sheet 12V Input, Efuse and 3p3V Utility
R18 R27 = RSMD040203878: RES SMD 88.7KOHM 0.1% 1/16W 0402; Manufacturer: Yageo; CompType: Resistor SMD; Power (Watts): 0.063W, 1/16W; Temperature Coefficient: ±25ppm/°C; SizeX_mm: 1; SizeY_mm: 0.5; SizeZ_mm: 0.4
R19 R28 = RSMD040200551: RES SMD 12.4KOHM 0.1% 1/16W 0402; Manufacturer: Panasonic Electronic Components; CompType: Resistor SMD; Power (Watts): 0.063W, 1/16W; Temperature Coefficient: ±25ppm/°C; SizeX_mm: 1; SizeY_mm: 0.5; SizeZ_mm: 0.4
R20 R29 = RSMD040200519: as R8 on sheet 12V Input, Efuse and 3p3V Utility
R21 R22 R30 = RSMD040200004: RES 0 OHM JUMPER 0402 SMD; Manufacturer: Panasonic Electronic Components; CompType: Resistor SMD; Power (Watts): 0.1W, 1/10W; Temperature Coefficient: -100/ +600ppm/°C; SizeX_mm: 1; SizeY_mm: 0.5; SizeZ_mm: 0.4
U4 U6 = INA180B1IDBVR: 26V, 350kHz current sense amplifier; Manufacturer: Texas Instruments; Alt PartNumber: INA180B1IDBVT; CompType: Current Amplifier
U5 U7 = cmp00446: 2-A, ultra-low noise ultra-high PSRR RF voltage regulator; PartNumber: TPS7A9601DSCR; Manufacturer: Texas Instruments; CompType: LDO

## Sheet Power Sense ADC.SchDoc: Sense ADC
size 431 x 279 mm; Date: Not shown in title block; ApprovedBy: Not shown in title block; CheckedBy: Not shown in title block; Author: Not shown in title block; CompanyName: Not shown in title block; Engineer: Not shown in title block; Organization: Not shown in title block; Address1: Not shown in title block; Address2: Not shown in title block; Address3: Not shown in title block; Address4: Not shown in title block; DocumentNumber: 1; Revision: Use project parameter SCH_Rev; SheetNumber: 5; SheetTotal: 14; PageSetup: Record=PageOptions¦CenterHorizontal=True¦CenterVertical=True¦PrintScale=1.00¦XCorrection=1.00¦YCorrection=1.00¦PrintKind=0¦BorderSize=5000000¦LeftOffset=0¦BottomOffset=0¦Orientation=2¦PaperLength=1000¦PaperWidth=1000¦Scale=100¦PaperSource=15¦PrintQuality=600¦MediaType=1¦DitherType=10¦PaperKind=Letter¦PrintScaleMode=1
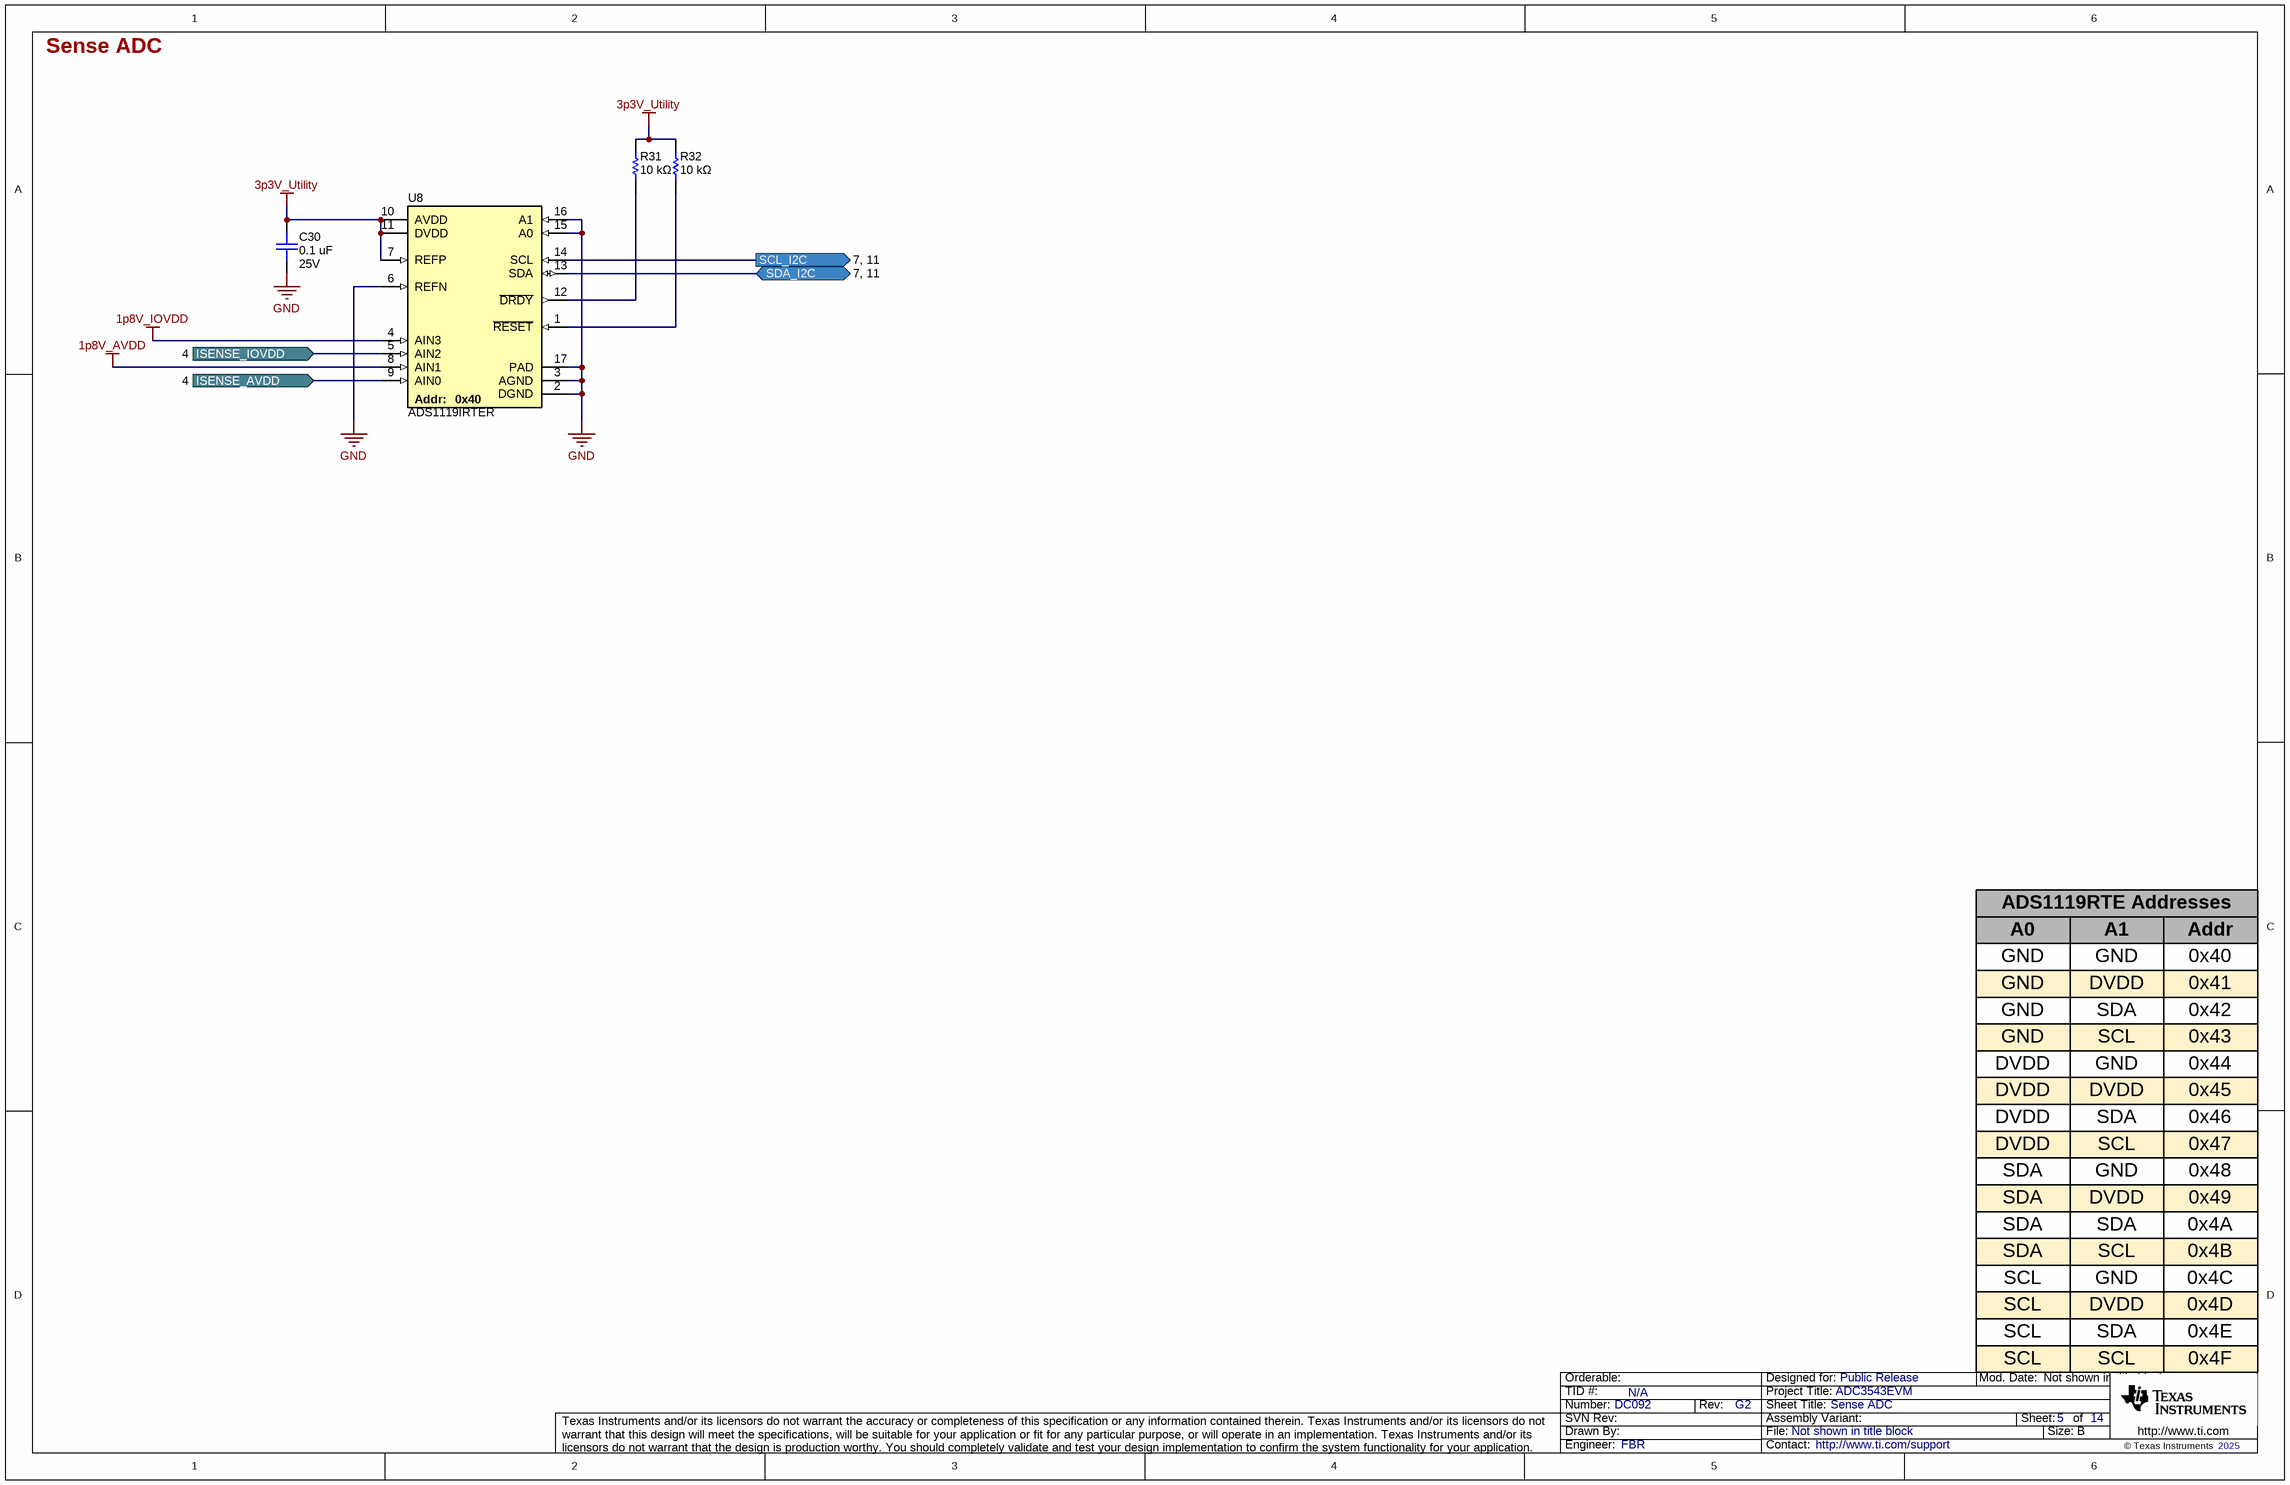
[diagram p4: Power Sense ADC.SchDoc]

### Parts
C30  value 0.1 uF  Voltage - Rated: 25V  [0402L_cap]  (hidden comment: GRT155R71E104KE01J)
R31  value 10 kΩ  [0402L]  (hidden comment: ERA-2AEB103X)
R32  value 10 kΩ  [0402L]  (hidden comment: ERA-2AEB103X)
U8  ADS1119IRTER  Addresss: 0x40  [RTE0016D]

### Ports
ISENSE_AVDD (in, see 4), ISENSE_IOVDD (in, see 4), SCL_I2C (out, see 7, 11), SDA_I2C (bidir, see 7, 11)

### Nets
1p8V_AVDD: U8.8(AIN1)
1p8V_IOVDD: U8.4(AIN3)
3p3V_Utility: C30.2 R31.2 R32.2 U8.7(REFP) U8.10(AVDD) U8.11(DVDD)
GND: C30.1 U8.2(DGND) U8.3(AGND) U8.6(REFN) U8.15(A0) U8.16(A1) U8.17(PAD)
ISENSE_AVDD: U8.9(AIN0) ; port ISENSE_AVDD
ISENSE_IOVDD: U8.5(AIN2) ; port ISENSE_IOVDD
SCL_I2C: U8.14(SCL) ; port SCL_I2C
SDA_I2C: U8.13(SDA) ; port SDA_I2C
NetR31_1: R31.1 U8.12(~{DRDY})
NetR32_1: R32.1 U8.1(~{RESET})

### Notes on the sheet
- A0
- GND
- ADS1119RTE Addresses
- A1
- Addr
- 0x40
- DVDD
- SDA
- 0x41
- 0x42
- SCL
- 0x43
- 0x44
- 0x45
- 0x46
- 0x47
- 0x48
- 0x49
- 0x4A
- 0x4B
- 0x4C
- 0x4D
- 0x4E
- 0x4F

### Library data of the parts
C30 = capcc09401: as C17 on sheet Power LDO
R31 R32 = RSMD040200315: as R5 on sheet 12V Input, Efuse and 3p3V Utility
U8 = ADS1119IRTER: 16-Bit, 4-Channel, 1-kSPS, Delta-Sigma ADC with I2C Interface, RTE0016D (WQFN-16); Alternate PartNumber: ADS1119IRTET; Alternate Manufacturer: Texas Instruments; SizeAreaWB_mm2: 16; SizeZ_mm: 0.8; SizeX_mm: 3; SizeArea_mm2: 9; AEC Qualified: N; AEC Category: Q200

## Sheet USB Control FTDI.SchDoc: FTDI Control
size 431 x 279 mm; Date: Not shown in title block; ApprovedBy: Not shown in title block; CheckedBy: Not shown in title block; Author: Not shown in title block; CompanyName: Not shown in title block; Engineer: Not shown in title block; Organization: Not shown in title block; Address1: Not shown in title block; Address2: Not shown in title block; Address3: Not shown in title block; Address4: Not shown in title block; DocumentNumber: 1; Revision: Use project parameter SCH_Rev; SheetNumber: 6; SheetTotal: 14; PageSetup: Record=PageOptions¦CenterHorizontal=True¦CenterVertical=True¦PrintScale=1.00¦XCorrection=1.00¦YCorrection=1.00¦PrintKind=0¦BorderSize=5000000¦LeftOffset=0¦BottomOffset=0¦Orientation=2¦PaperLength=1000¦PaperWidth=1000¦Scale=100¦PaperSource=15¦PrintQuality=600¦MediaType=1¦DitherType=10¦PaperKind=Letter¦PrintScaleMode=1
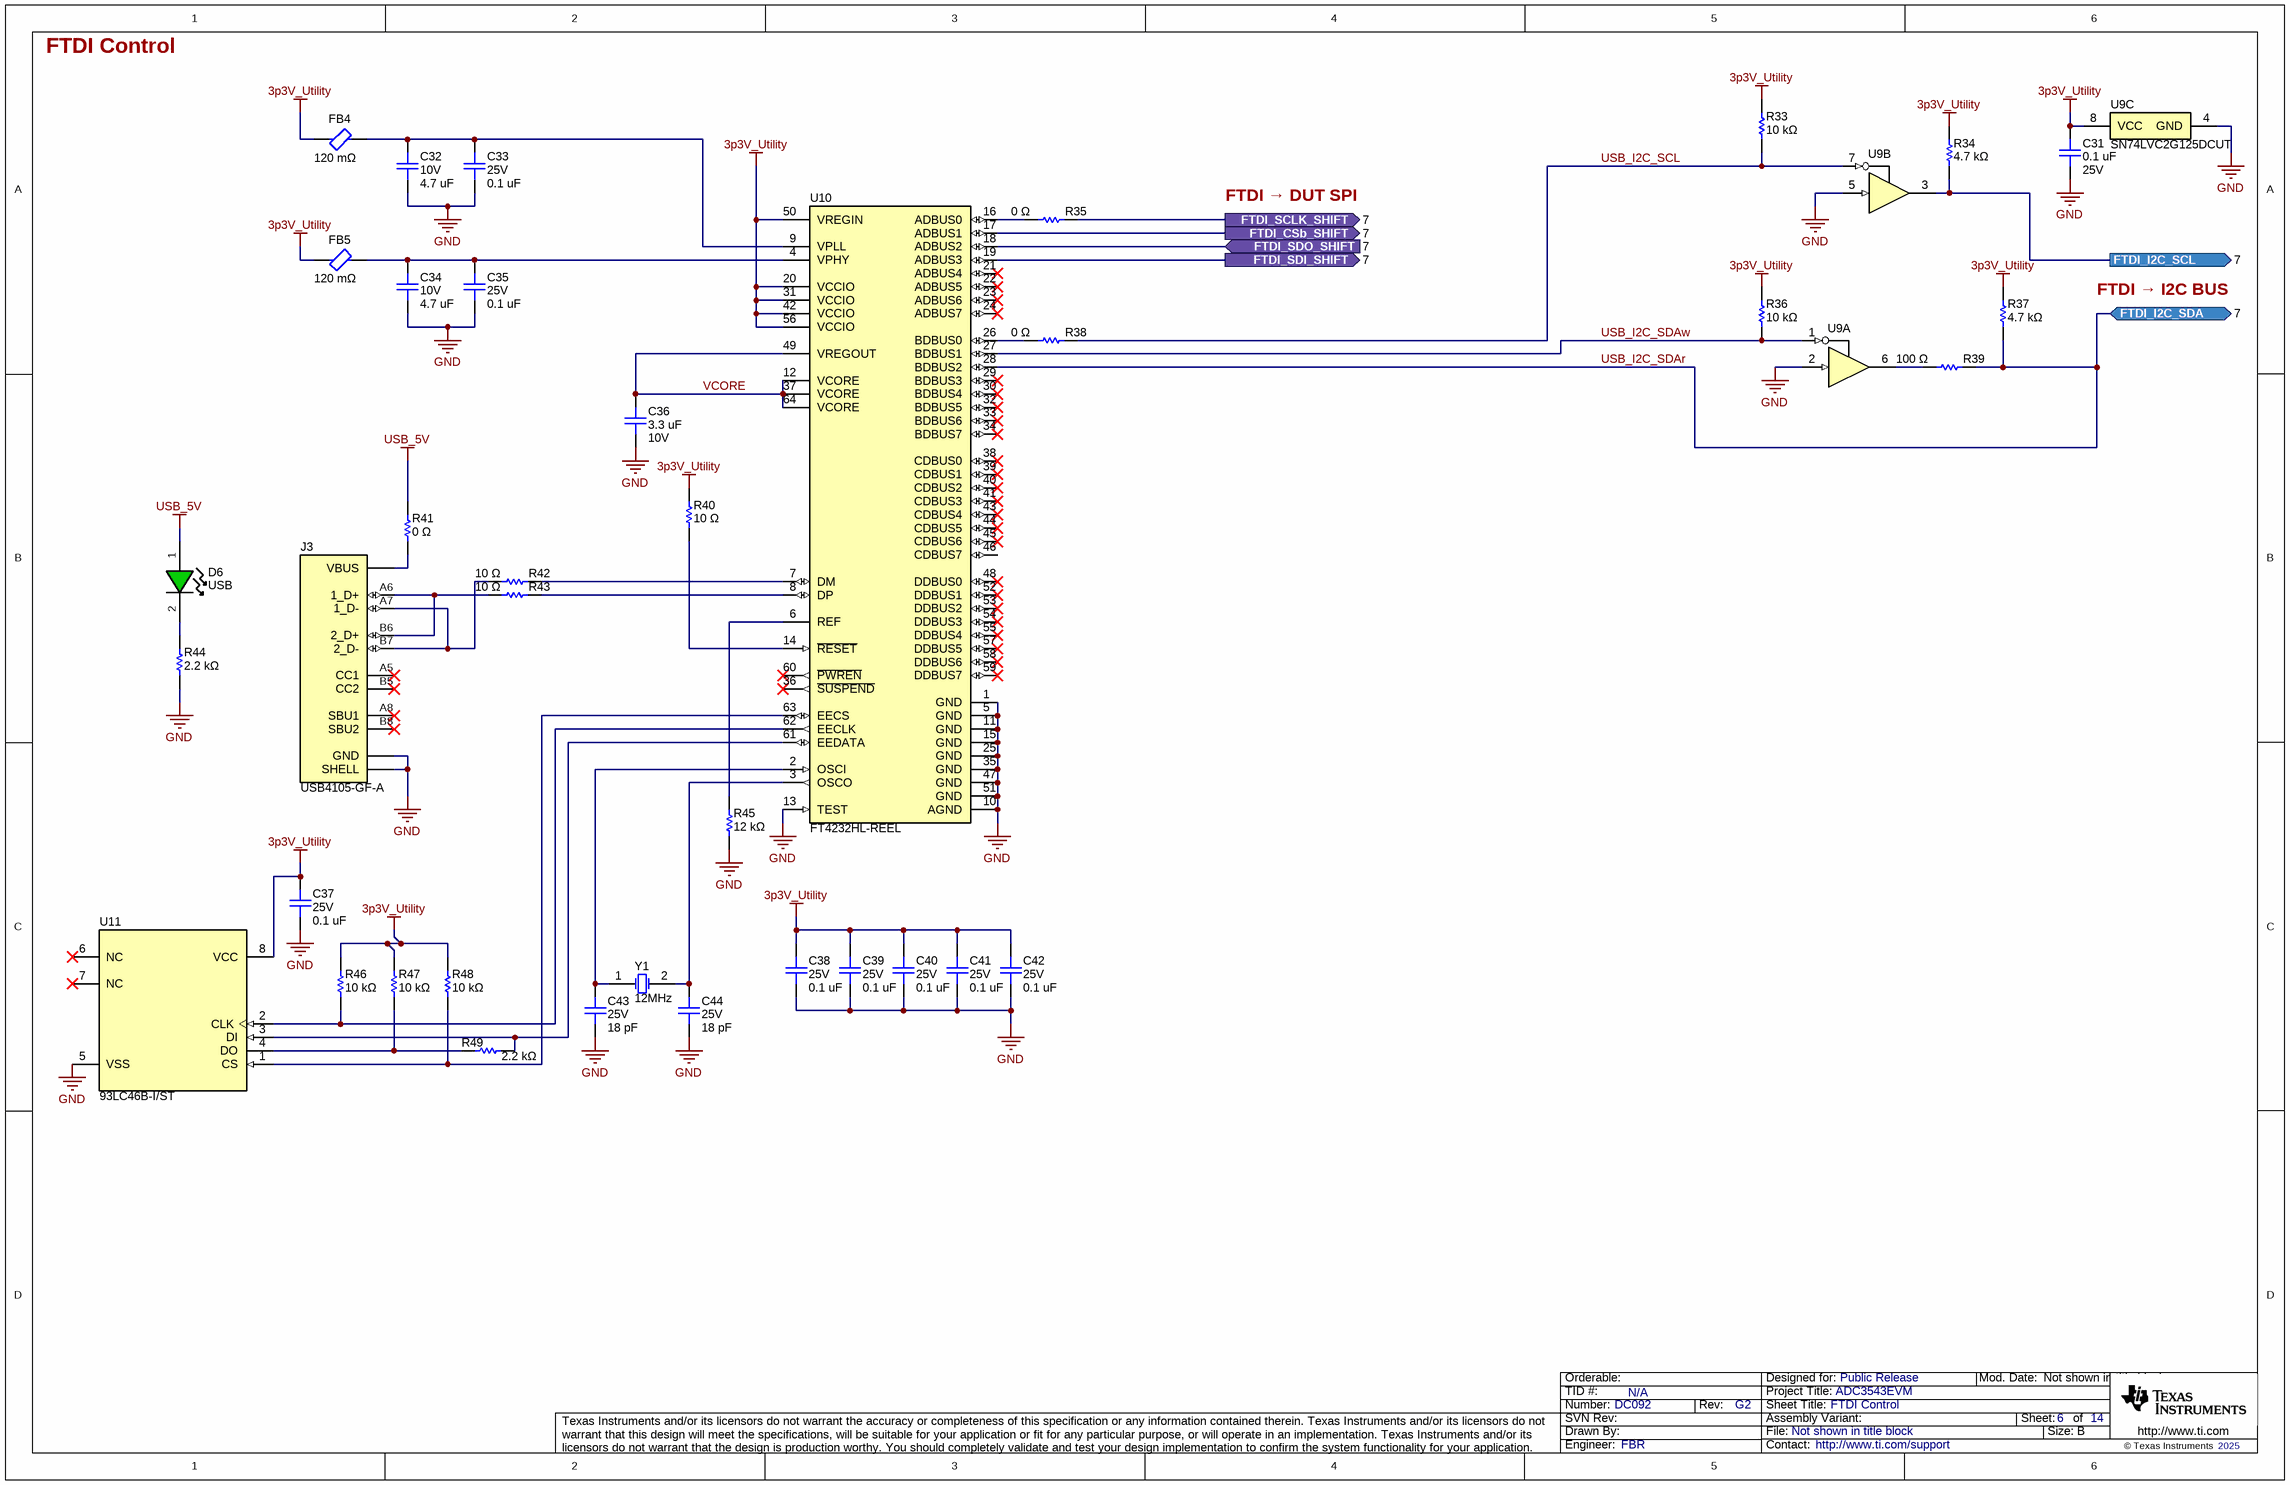
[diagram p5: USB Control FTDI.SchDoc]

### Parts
C31  value 0.1 uF  Voltage - Rated: 25V  [0402L_cap]  (hidden comment: GRT155R71E104KE01J)
C32  value 4.7 uF  Voltage - Rated: 10V  [0402L_cap]  (hidden comment: C1005X5R1A475K050BC)
C33  value 0.1 uF  Voltage - Rated: 25V  [0402L_cap]  (hidden comment: GRT155R71E104KE01J)
C34  value 4.7 uF  Voltage - Rated: 10V  [0402L_cap]  (hidden comment: C1005X5R1A475K050BC)
C35  value 0.1 uF  Voltage - Rated: 25V  [0402L_cap]  (hidden comment: GRT155R71E104KE01J)
C36  value 3.3 uF  Voltage - Rated: 10V  [0603L_cap]  (hidden comment: CGA3E1X5R1A335K080AC)
C37  value 0.1 uF  Voltage - Rated: 25V  [0402L_cap]  (hidden comment: GRT155R71E104KE01J)
C38  value 0.1 uF  Voltage - Rated: 25V  [0402L_cap]  (hidden comment: GRT155R71E104KE01J)
C39  value 0.1 uF  Voltage - Rated: 25V  [0402L_cap]  (hidden comment: GRT155R71E104KE01J)
C40  value 0.1 uF  Voltage - Rated: 25V  [0402L_cap]  (hidden comment: GRT155R71E104KE01J)
C41  value 0.1 uF  Voltage - Rated: 25V  [0402L_cap]  (hidden comment: GRT155R71E104KE01J)
C42  value 0.1 uF  Voltage - Rated: 25V  [0402L_cap]  (hidden comment: GRT155R71E104KE01J)
C43  value 18 pF  Voltage - Rated: 25V  [0201_cap]  (hidden comment: GJM0336C1E180JB01J)
C44  value 18 pF  Voltage - Rated: 25V  [0201_cap]  (hidden comment: GJM0336C1E180JB01J)
D6  Text1: USB  [LED_LTST-C190-Green]  (hidden comment: LTST-C191TGKT)
FB4  DCR: 120 mΩ  [0402L]  (hidden comment: NFZ15SG151SN11D)
FB5  DCR: 120 mΩ  [0402L]  (hidden comment: NFZ15SG151SN11D)
J3  USB4105-GF-A  [FP-USB4105-GF-A_CONN_USB_9MM58_7MM53-MFG]
R33  value 10 kΩ  [0402L]  (hidden comment: ERA-2AEB103X)
R34  value 4.7 kΩ  [0402L]  (hidden comment: ERJ-2RKF4701X)
R35  value 0 Ω  [0201]  (hidden comment: ERJ-1GN0R00C)
R36  value 10 kΩ  [0402L]  (hidden comment: ERA-2AEB103X)
R37  value 4.7 kΩ  [0402L]  (hidden comment: ERJ-2RKF4701X)
R38  value 0 Ω  [0201]  (hidden comment: ERJ-1GN0R00C)
R39  value 100 Ω  [0402L]  (hidden comment: ERJ-2RKF1000X)
R40  value 10 Ω  [0402L]  (hidden comment: ERJ-2GEJ100X)
R41  value 0 Ω  [0805L]  (hidden comment: ERJ-6GEY0R00V)
R42  value 10 Ω  [0402L]  (hidden comment: ERJ-2GEJ100X)
R43  value 10 Ω  [0402L]  (hidden comment: ERJ-2GEJ100X)
R44  value 2.2 kΩ  [0402L]  (hidden comment: ERJ-2GEJ222X)
R45  value 12 kΩ  [0402L]  (hidden comment: ERJ-2RKF1202X)
R46  value 10 kΩ  [0402L]  (hidden comment: ERA-2AEB103X)
R47  value 10 kΩ  [0402L]  (hidden comment: ERA-2AEB103X)
R48  value 10 kΩ  [0402L]  (hidden comment: ERA-2AEB103X)
R49  value 2.2 kΩ  [0402L]  (hidden comment: ERJ-2GEJ222X)
U9  SN74LVC2G125DCUT  [DCU0008A]  (value not drawn)  (parts A,B,C of 3)
U10  FT4232HL-REEL  [LQFP64-MFG]
U11  93LC46B-I/ST  [TSSOP-8]
Y1  Text1: 12MHz  [XTAL_ABM3]  (hidden comment: ABM3-12.000MHZ-D2Y-T)

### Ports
FTDI_CSb_SHIFT (out, see 7), FTDI_I2C_SCL (out, see 7), FTDI_I2C_SDA (bidir, see 7), FTDI_SCLK_SHIFT (out, see 7), FTDI_SDI_SHIFT (out, see 7), FTDI_SDO_SHIFT (in, see 7)

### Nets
3p3V_Utility: C31.2 C37.2 C38.2 C39.2 C40.2 C41.2 C42.2 FB4.1 FB5.1 R33.2 R34.1 R36.2 R37.1 R40.2 R46.2 R47.2 R48.2 U9.8(VCC) U10.20(VCCIO) U10.31(VCCIO) U10.42(VCCIO) U10.50(VREGIN) U10.56(VCCIO) U11.8(VCC)
GND: C31.1 C32.1 C33.1 C34.1 C35.1 C36.1 C37.1 C38.1 C39.1 C40.1 C41.1 C42.1 C43.1 C44.1 J3.1,2,3,4(SHELL) J3.A1,B1(GND) R44.1 R45.1 U9.2(1A) U9.4(GND) U9.5(2A) U10.1(GND) U10.5(GND) U10.10(AGND) U10.11(GND) U10.13(TEST) U10.15(GND) U10.25(GND) U10.35(GND) U10.47(GND) U10.51(GND) U11.5(VSS)
USB_5V: D6.1(A) R41.2
FTDI_CSb_SHIFT: U10.17(ADBUS1) ; port FTDI_CSb_SHIFT
FTDI_I2C_SCL: R34.2 U9.3(2Y) ; port FTDI_I2C_SCL
FTDI_SCLK_SHIFT: R35.2 ; port FTDI_SCLK_SHIFT
FTDI_SDI_SHIFT: U10.19(ADBUS3) ; port FTDI_SDI_SHIFT
FTDI_SDO_SHIFT: U10.18(ADBUS2) ; port FTDI_SDO_SHIFT
USB_I2C_SCL: R33.1 R38.2 U9.7(2~{OE})
USB_I2C_SDAr: R37.2 R39.2 U10.28(BDBUS2) ; port FTDI_I2C_SDA
USB_I2C_SDAw: R36.1 U9.1(1~{OE}) U10.27(BDBUS1)
VCORE: C36.2 U10.12(VCORE) U10.37(VCORE) U10.49(VREGOUT) U10.64(VCORE)
NetC32_2: C32.2 C33.2 FB4.2 U10.9(VPLL)
NetC34_2: C34.2 C35.2 FB5.2 U10.4(VPHY)
NetC43_2: C43.2 U10.2(OSCI) Y1.1(OSC1)
NetC44_2: C44.2 U10.3(OSCO) Y1.2(OSC2)
NetD6_2: D6.2(K) R44.2
NetJ3_A4,B4: J3.A4,B4(VBUS) R41.1
NetJ3_A6: J3.A6(1_D+) J3.B6(2_D+) R43.1
NetJ3_A7: J3.A7(1_D-) J3.B7(2_D-) R42.1
NetR35_1: R35.1 U10.16(ADBUS0)
NetR38_1: R38.1 U10.26(BDBUS0)
NetR39_1: R39.1 U9.6(1Y)
NetR40_1: R40.1 U10.14(~{RESET})
NetR42_2: R42.2 U10.7(DM)
NetR43_2: R43.2 U10.8(DP)
NetR45_2: R45.2 U10.6(REF)
NetR46_1: R46.1 U10.62(EECLK) U11.2(CLK)
NetR47_1: R47.1 R49.1 U11.4(DO)
NetR48_1: R48.1 U10.63(EECS) U11.1(CS)
NetR49_2: R49.2 U10.61(EEDATA) U11.3(DI)

Not connected (* = marked no-connect by the designer): J3 A5(CC1)* A8(SBU1)* B5(CC2)* B8(SBU2)*; U10 21(ADBUS4)* 22(ADBUS5)* 23(ADBUS6)* 24(ADBUS7)* 29(BDBUS3)* 30(BDBUS4)* 32(BDBUS5)* 33(BDBUS6)* 34(BDBUS7)* 36(~{SUSPEND})* 38(CDBUS0)* 39(CDBUS1)* 40(CDBUS2)* 41(CDBUS3)* 43(CDBUS4)* 44(CDBUS5)* 45(CDBUS6)* 46(CDBUS7) 48(DDBUS0)* 52(DDBUS1)* 53(DDBUS2)* 54(DDBUS3)* 55(DDBUS4)* 57(DDBUS5)* 58(DDBUS6)* 59(DDBUS7)* 60(~{PWREN})*; U11 6(NC)* 7(NC)*

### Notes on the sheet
- FTDI → DUT SPI
- FTDI → I2C BUS

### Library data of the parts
C31 C33 C35 C37-C42 = capcc09401: as C17 on sheet Power LDO
C32 C34 = capcc03298: CAP CER 4.7UF 10V X5R 0402; Manufacturer: TDK Corporation; CompType: Capacitor Ceramic; Tolerance: ±10%; SizeX_mm: 1; SizeY_mm: 0.5; SizeZ_mm: 0.65
C36 = capcc03130: CAP CER 3.3UF 10V X5R 0603; Manufacturer: TDK Corporation; CompType: Capacitor Ceramic; Tolerance: ±10%; SizeX_mm: 1.6; SizeY_mm: 0.8; SizeZ_mm: 0.9
C43 C44 = capcc08580: CAP CER 18PF 25V C0H 0201; Manufacturer: Murata Electronics; CompType: Capacitor Ceramic; Tolerance: ±5%; SizeX_mm: 0.6; SizeY_mm: 0.3; SizeZ_mm: 0.33
D6 = cmp00247: as D1 on sheet 12V Input, Efuse and 3p3V Utility
FB4 FB5 = dcp00209: 0402 (1005) 150OHM (TYP.) 1000MA; Manufacturer: Murata Electronics; Current: 1A
J3 = USB4105-GF-A: USB - C (Type - C) USB 2.0 Receptacle Connector 24 Position Surface Mount, Right Angle; Through Hole; Manufacturer: GCT; CompType: USB C
R33 R36 R46-R48 = RSMD040200315: as R5 on sheet 12V Input, Efuse and 3p3V Utility
R34 R37 = RSMD040202594: RES SMD 4.7K OHM 1% 1/10W 0402; Manufacturer: Panasonic Electronic Components; CompType: Resistor SMD; Power (Watts): 0.1W, 1/10W; Temperature Coefficient: ±100ppm/°C; SizeX_mm: 1; SizeY_mm: 0.5; SizeZ_mm: 0.4
R35 R38 = RSMD020101699: RES SMD 0 OHM JUMPER 1/20W 0201; Manufacturer: Panasonic Electronic Components; CompType: Resistor SMD; Power (Watts): 0.05W, 1/20W
R39 = RSMD040200375: RES SMD 100 OHM 1% 1/10W 0402; Manufacturer: Panasonic Electronic Components; CompType: Resistor SMD; Power (Watts): 0.1W, 1/10W; Temperature Coefficient: ±100ppm/°C; SizeX_mm: 1; SizeY_mm: 0.5; SizeZ_mm: 0.4
R40 R42 R43 = RSMD040200327: RES SMD 10 OHM 5% 1/10W 0402; Manufacturer: Panasonic Electronic Components; CompType: Resistor SMD; Power (Watts): 0.1W, 1/10W; Temperature Coefficient: ±200ppm/°C; SizeX_mm: 1; SizeY_mm: 0.5; SizeZ_mm: 0.4
R41 = RSMD080510615: RES SMD 0 OHM JUMPER 1/8W 0805; Manufacturer: Panasonic Electronic Components; CompType: Resistor SMD; Power (Watts): 0.125W, 1/8W; SizeX_mm: 2; SizeY_mm: 1.25; SizeZ_mm: 0.7
R44 R49 = RSMD040201206: RES SMD 2.2K OHM 5% 1/10W 0402; Manufacturer: Panasonic Electronic Components; CompType: Resistor SMD; Power (Watts): 0.1W, 1/10W; Temperature Coefficient: ±200ppm/°C; SizeX_mm: 1; SizeY_mm: 0.5; SizeZ_mm: 0.4
R45 = RSMD040200519: as R8 on sheet 12V Input, Efuse and 3p3V Utility
U9 = SN74LVC2G125DCUT: Dual Bus Buffer Gate with 3-State Outputs, DCU0008A (VSSOP-8); Manufacturer: Texas Instruments; F @ Nom Voltage(Max)(Mhz): 150; VCC(Min)(V): 1.65; Bits(#): 2; Output Type: CMOS; Technology Family: LVC; Rating: Catalog; tpd @ Nom Voltage(Max)(ns): 9.1,4.8,4.3,3.7; 3-State Output: Yes; Schmitt Trigger: No; Logic: True; Voltage(Nom)(V): 1.8,2.5,3.3,5; Output Drive (IOL/IOH)(Max)(mA): 32/-32; ICC @ Nom Voltage(Max)(mA): 0.01; Input Type: CMOS/TTL; VCC(Max)(V): 5.5; AEC Category: Q200; AEC Qualified: N; CompType: IC; SizeAreaWB_mm2: 12.6; SizeArea_mm2: 6.4; SizeX_mm: 3.2; SizeY_mm: 2.0; SizeZ_mm: 0.9
U10 = cmp00204: USB Interface IC USB HS to Quad UART/ SPI/JTAG/I2C LQFP-6; Manufacturer: FTDI; Alt PartNumber: FT4232HL-TRAY; Symbol Name: SYM-FT4232HL-REEL; CompType: uC
U11 = cmp00156: 1K Microwire Compatible Serial EEPROM; Manufacturer: Microchip Technology; SymbolCreator: Altium; SizeArea_mm2: 19.2; SizeAreaWB_mm2: 42
Y1 = cmp00323: 12 MHz ±20ppm Crystal 18pF 60 Ohms 2-SMD, No Lead; Manufacturer: Abracon LLC; CompType: XO

## Sheet Comms LVL Shift and MUX.SchDoc: Comms Lvl Shift & Mux
size 431 x 279 mm; Date: Not shown in title block; ApprovedBy: Not shown in title block; CheckedBy: Not shown in title block; Author: Not shown in title block; CompanyName: Not shown in title block; Engineer: Not shown in title block; Organization: Not shown in title block; Address1: Not shown in title block; Address2: Not shown in title block; Address3: Not shown in title block; Address4: Not shown in title block; DocumentNumber: 1; Revision: Use project parameter SCH_Rev; SheetNumber: 7; SheetTotal: 15; PageSetup: Record=PageOptions¦CenterHorizontal=True¦CenterVertical=True¦PrintScale=1.00¦XCorrection=1.00¦YCorrection=1.00¦PrintKind=0¦BorderSize=5000000¦LeftOffset=0¦BottomOffset=0¦Orientation=2¦PaperLength=1000¦PaperWidth=1000¦Scale=100¦PaperSource=15¦PrintQuality=600¦MediaType=1¦DitherType=10¦PaperKind=Letter¦PrintScaleMode=1
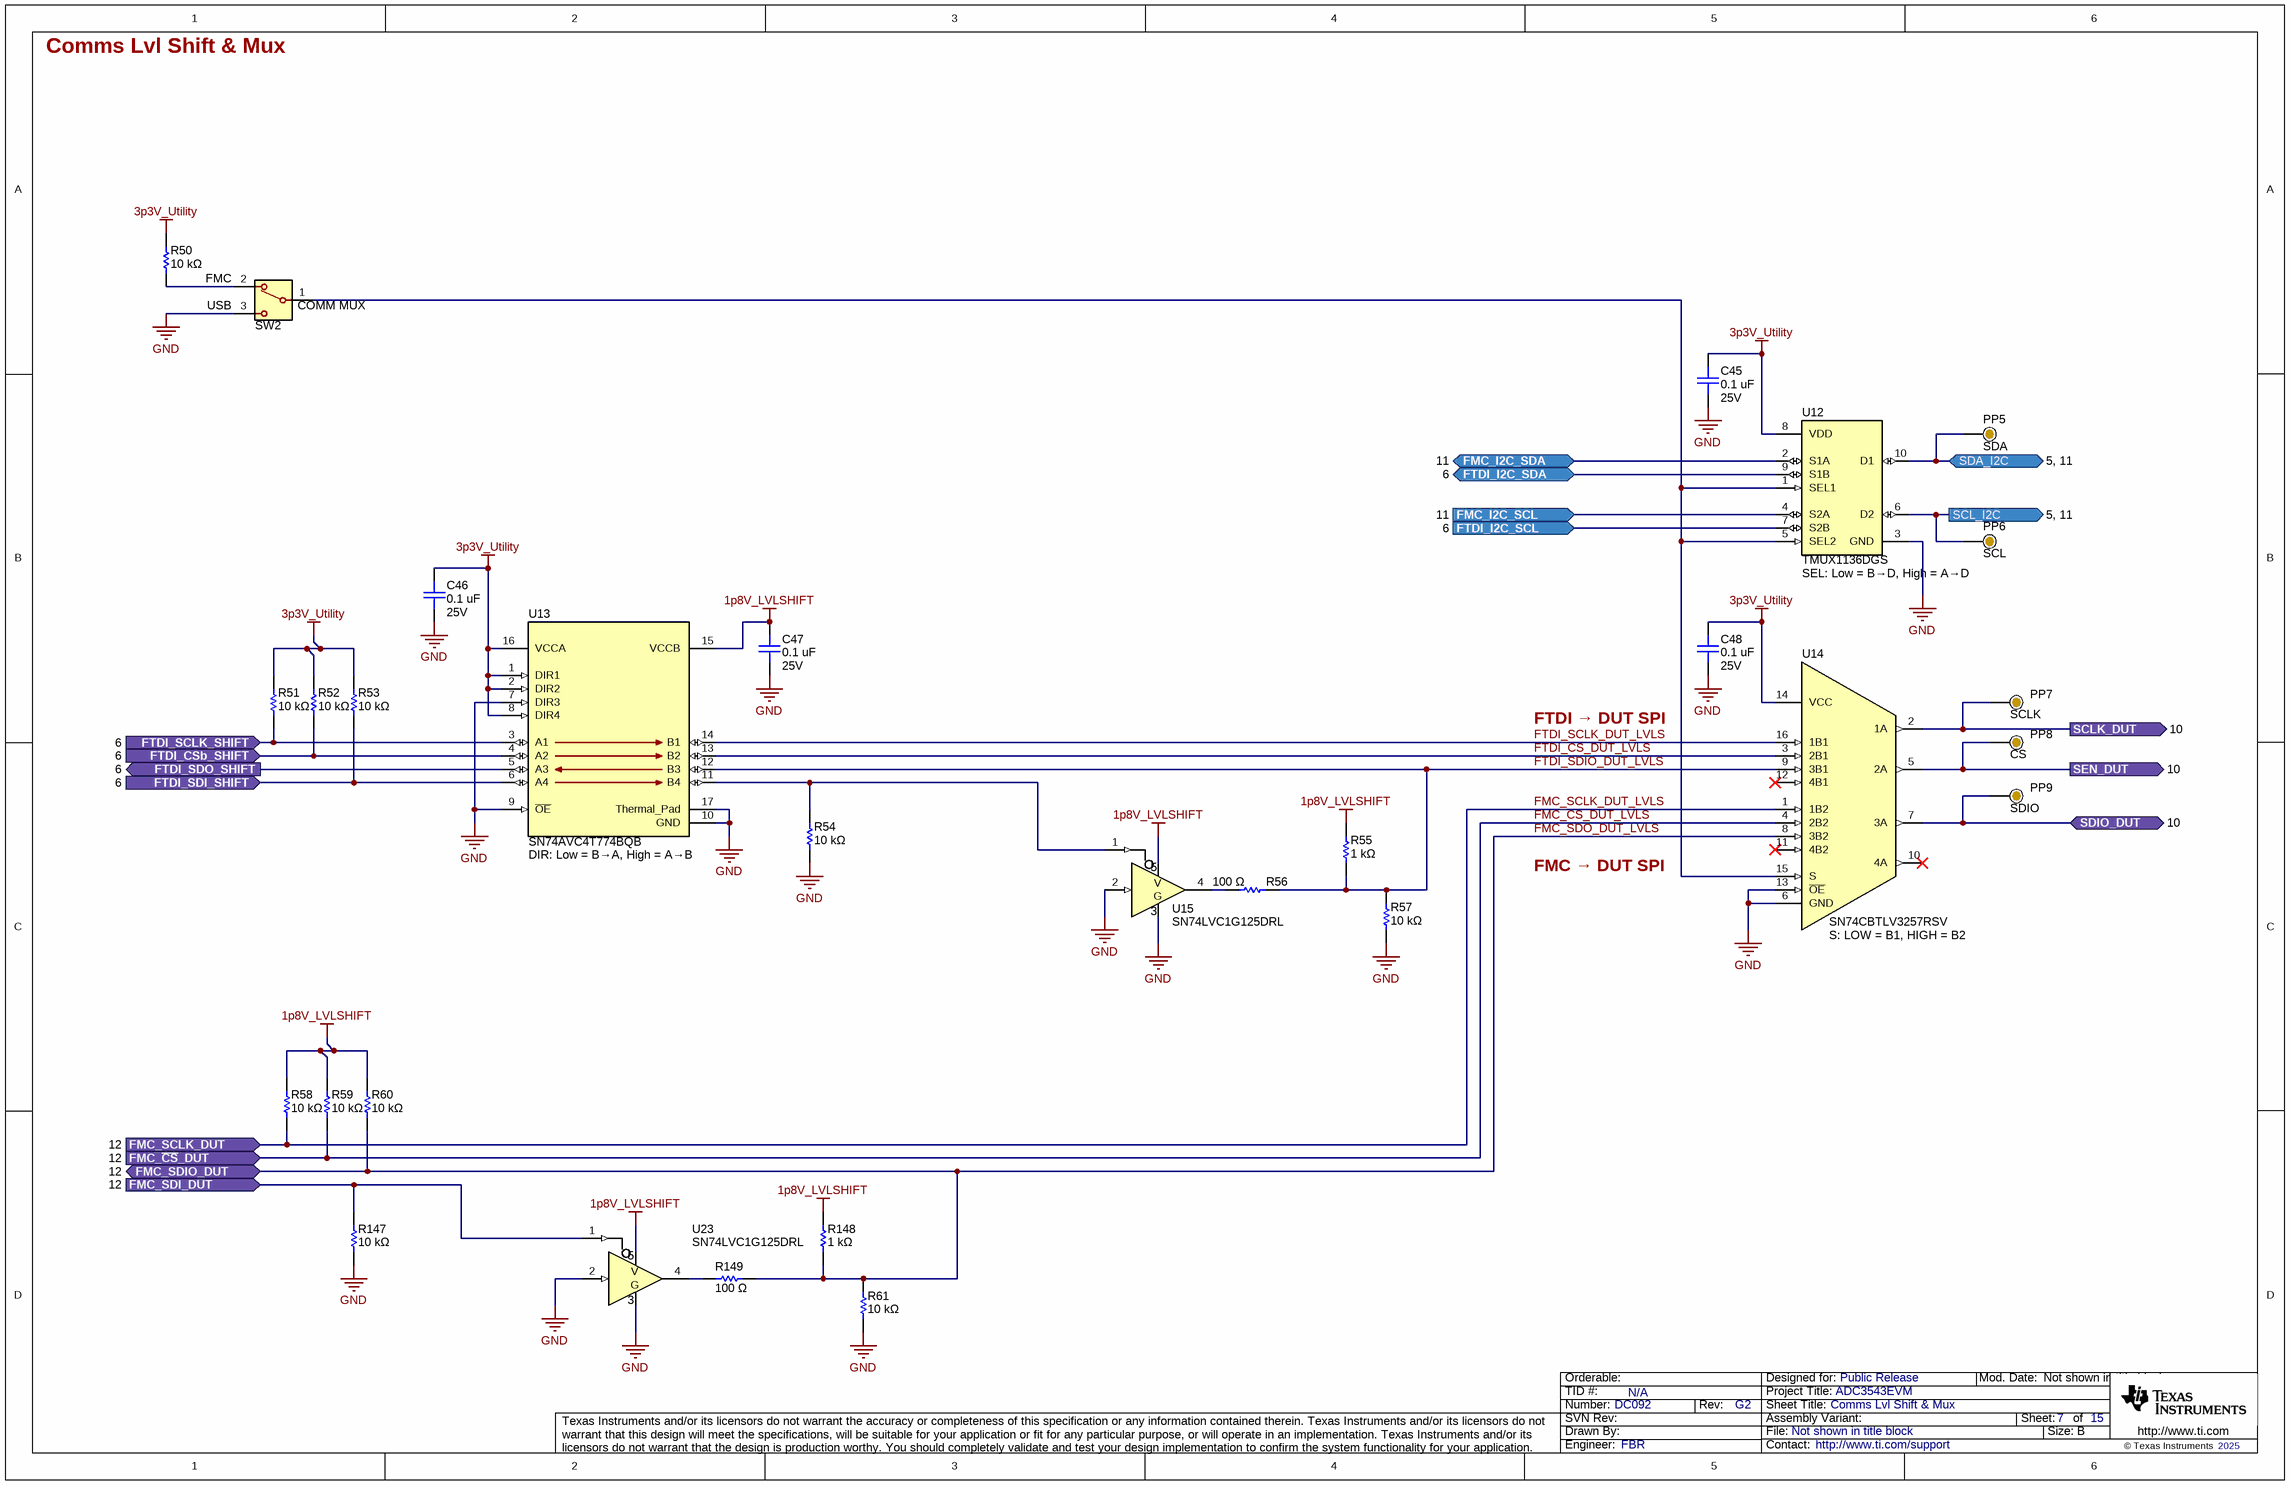
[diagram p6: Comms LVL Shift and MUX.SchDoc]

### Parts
C45  value 0.1 uF  Voltage - Rated: 25V  [0402L_cap]  (hidden comment: GRT155R71E104KE01J)
C46  value 0.1 uF  Voltage - Rated: 25V  [0402L_cap]  (hidden comment: GRT155R71E104KE01J)
C47  value 0.1 uF  Voltage - Rated: 25V  [0402L_cap]  (hidden comment: GRT155R71E104KE01J)
C48  value 0.1 uF  Voltage - Rated: 25V  [0402L_cap]  (hidden comment: GRT155R71E104KE01J)
PP5  Text1: SDA  [ProbePoint_TH_40mil]  (hidden comment: Probe Point)  (no BOM)
PP6  Text1: SCL  [ProbePoint_TH_40mil]  (hidden comment: Probe Point)  (no BOM)
PP7  Text1: SCLK  [ProbePoint_TH_40mil]  (hidden comment: Probe Point)  (no BOM)
PP8  Text1: CS  [ProbePoint_TH_40mil]  (hidden comment: Probe Point)  (no BOM)
PP9  Text1: SDIO  [ProbePoint_TH_40mil]  (hidden comment: Probe Point)  (no BOM)
R50  value 10 kΩ  [0402L]  (hidden comment: ERA-2AEB103X)
R51  value 10 kΩ  [0402L]  (hidden comment: ERA-2AEB103X)
R52  value 10 kΩ  [0402L]  (hidden comment: ERA-2AEB103X)
R53  value 10 kΩ  [0402L]  (hidden comment: ERA-2AEB103X)
R54  value 10 kΩ  [0402L]  (hidden comment: ERA-2AEB103X)
R55  value 1 kΩ  [0402L]  (hidden comment: ERJ-U02J102X)
R56  value 100 Ω  [0402L]  (hidden comment: ERJ-2RKF1000X)
R57  value 10 kΩ  [0402L]  (hidden comment: ERA-2AEB103X)
R58  value 10 kΩ  [0402L]  (hidden comment: ERA-2AEB103X)
R59  value 10 kΩ  [0402L]  (hidden comment: ERA-2AEB103X)
R60  value 10 kΩ  [0402L]  (hidden comment: ERA-2AEB103X)
R61  value 10 kΩ  [0402L]  (hidden comment: ERA-2AEB103X)
R147  value 10 kΩ  [0402L]  (hidden comment: ERA-2AEB103X)
R148  value 1 kΩ  [0402L]  (hidden comment: ERJ-U02J102X)
R149  value 100 Ω  [0402L]  (hidden comment: ERJ-2RKF1000X)
SW2  Text1: COMM MUX  Text2: FMC  Text3: USB  [450301014042]  (hidden comment: cmp00353)
U12  TMUX1136DGS  Text1: SEL: Low = B→D, High = A→D  [DQA0010A]
U13  SN74AVC4T774BQB  Text1: DIR: Low = B→A, High = A→B  [BQB0016A-MFG]
U14  SN74CBTLV3257RSV  Text1: S: LOW = B1, HIGH = B2  [RSV0016A]
U15  SN74LVC1G125DRL  [DRL0005A]
U23  SN74LVC1G125DRL  [DRL0005A]

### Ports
FMC_I2C_SCL (in, see 11), FMC_I2C_SDA (bidir, see 11), FMC_SCLK_DUT (in, see 12), FMC_SDI_DUT (in, see 12), FMC_SDIO_DUT (bidir, see 12), FMC_~{CS}_DUT (in, see 12), FTDI_CSb_SHIFT (in, see 6), FTDI_I2C_SCL (in, see 6), FTDI_I2C_SDA (bidir, see 6), FTDI_SCLK_SHIFT (in, see 6), FTDI_SDI_SHIFT (in, see 6), FTDI_SDO_SHIFT (out, see 6), SCL_I2C (out, see 5, 11), SCLK_DUT (out, see 10), SDA_I2C (bidir, see 5, 11), SDIO_DUT (bidir, see 10), SEN_DUT (out, see 10)

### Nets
1p8V_LVLSHIFT: C47.2 R55.1 R58.2 R59.2 R60.2 R148.1 U13.15(VCCB) U15.5(VCC) U23.5(VCC)
3p3V_Utility: C45.2 C46.2 C48.2 R50.2 R51.2 R52.2 R53.2 U12.8(VDD) U13.1(DIR1) U13.2(DIR2) U13.8(DIR4) U13.16(VCCA) U14.14(VCC)
GND: C45.1 C46.1 C47.1 C48.1 R54.1 R57.2 R61.2 R147.1 SW2.3 U12.3(GND) U13.7(DIR3) U13.9(~{OE}) U13.10(GND) U13.17(Thermal_Pad) U14.6(GND) U14.13(~{OE}) U15.2(A) U15.3(GND) U23.2(A) U23.3(GND)
FMC_~{CS}_DUT_LVLS: R59.1 U14.4(2B2) ; port FMC_~{CS}_DUT
FMC_I2C_SCL: U12.4(S2A) ; port FMC_I2C_SCL
FMC_I2C_SDA: U12.2(S1A) ; port FMC_I2C_SDA
FMC_SCLK_DUT_LVLS: R58.1 U14.1(1B2) ; port FMC_SCLK_DUT
FMC_SDI_DUT: R147.2 U23.1(~{OE}) ; port FMC_SDI_DUT
FMC_SDO_DUT_LVLS: R60.1 R61.1 R148.2 R149.2 U14.8(3B2) ; port FMC_SDIO_DUT
FTDI_~{CS}_DUT_LVLS: U13.13(B2) U14.3(2B1)
FTDI_CSb_SHIFT: R52.1 U13.4(A2) ; port FTDI_CSb_SHIFT
FTDI_I2C_SCL: U12.7(S2B) ; port FTDI_I2C_SCL
FTDI_SCLK_DUT_LVLS: U13.14(B1) U14.16(1B1)
FTDI_SCLK_SHIFT: R51.1 U13.3(A1) ; port FTDI_SCLK_SHIFT
FTDI_SDI_SHIFT: R53.1 U13.6(A4) ; port FTDI_SDI_SHIFT
FTDI_SDIO_DUT_LVLS: R55.2 R56.2 R57.1 U13.12(B3) U14.9(3B1)
FTDI_SDO_SHIFT: U13.5(A3) ; port FTDI_SDO_SHIFT
SCL_I2C: PP6.1 U12.6(D2) ; port SCL_I2C
SCLK_DUT: PP7.1 U14.2(1A) ; port SCLK_DUT
SDA_I2C: PP5.1 U12.10(D1) ; port SDA_I2C
SDIO_DUT: PP9.1 U14.7(3A) ; port SDIO_DUT
SEN_DUT: PP8.1 U14.5(2A) ; port SEN_DUT
USB_I2C_SDAr: U12.9(S1B) ; port FTDI_I2C_SDA
NetR50_1: R50.1 SW2.2(COMM)
NetR54_2: R54.2 U13.11(B4) U15.1(~{OE})
NetR56_1: R56.1 U15.4(Y)
NetR149_1: R149.1 U23.4(Y)
NetSW2_1: SW2.1 U12.1(SEL1) U12.5(SEL2) U14.15(S)

Not connected (* = marked no-connect by the designer): U14 10(4A)* 11(4B2)* 12(4B1)*

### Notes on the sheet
- FTDI → DUT SPI
- FMC → DUT SPI

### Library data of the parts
C45-C48 = capcc09401: as C17 on sheet Power LDO
PP5-PP9 = Probe Point: as PP1 on sheet 12V Input, Efuse and 3p3V Utility
R50-R54 R57-R61 R147 = RSMD040200315: as R5 on sheet 12V Input, Efuse and 3p3V Utility
R55 R148 = RSMD040200011: RES 1K OHM 5% 1/10W 0402 SMD; Manufacturer: Panasonic Electronic Components; CompType: Resistor SMD; Power (Watts): 0.1W, 1/10W; Temperature Coefficient: ±200ppm/°C; SizeX_mm: 1; SizeY_mm: 0.5; SizeZ_mm: 0.4
R56 R149 = RSMD040200375: as R39 on sheet USB Control FTDI
SW2 = cmp00353: Switch Slide SPDT 12V, 500mA; Manufacturer: Wurth Elektronik
U12 = cmp00307: 5-V low-leakage-current, 2: 1, 2-channel precision analog switch; PartNumber: TMUX1136DQA; Manufacturer: Texas Instruments; CompType: MUX
U13 = cmp00170: Translation - Voltage Levels 4-bit dual-supply bus transceiver with 3-state outputs and independent direction control inputs; Manufacturer: Texas Instruments; Alt PartNumber: SN74AXC4T774BQB; CompType: Level Shifter
U14 = SN74CBTLV3257RSV: Low-Voltage 4-Bit 1-of-2 FET Multiplexer/Demultiplexe; PartNumber: SN74CBTLV3257RSVR; Manufacturer: Texas Instruments; UniqueID: cmp00269; CompType: MUX
U15 U23 = SN74LVC1G125DRL: Single Bus Buffer Gate With 3-State Outputs. Active low enable.; Manufacturer: Texas Instruments

## Sheet CLK and DCLKIN.SchDoc: CLK & DCLKIN
size 431 x 279 mm; Date: Not shown in title block; ApprovedBy: Not shown in title block; CheckedBy: Not shown in title block; Author: Not shown in title block; CompanyName: Not shown in title block; Engineer: Not shown in title block; Organization: Not shown in title block; Address1: Not shown in title block; Address2: Not shown in title block; Address3: Not shown in title block; Address4: Not shown in title block; DocumentNumber: 1; Revision: Use project parameter SCH_Rev; SheetNumber: 8; SheetTotal: 15; PageSetup: Record=PageOptions¦CenterHorizontal=True¦CenterVertical=True¦PrintScale=1.00¦XCorrection=1.00¦YCorrection=1.00¦PrintKind=0¦BorderSize=5000000¦LeftOffset=0¦BottomOffset=0¦Orientation=2¦PaperLength=1000¦PaperWidth=1000¦Scale=100¦PaperSource=15¦PrintQuality=600¦MediaType=1¦DitherType=10¦PaperKind=Letter¦PrintScaleMode=1
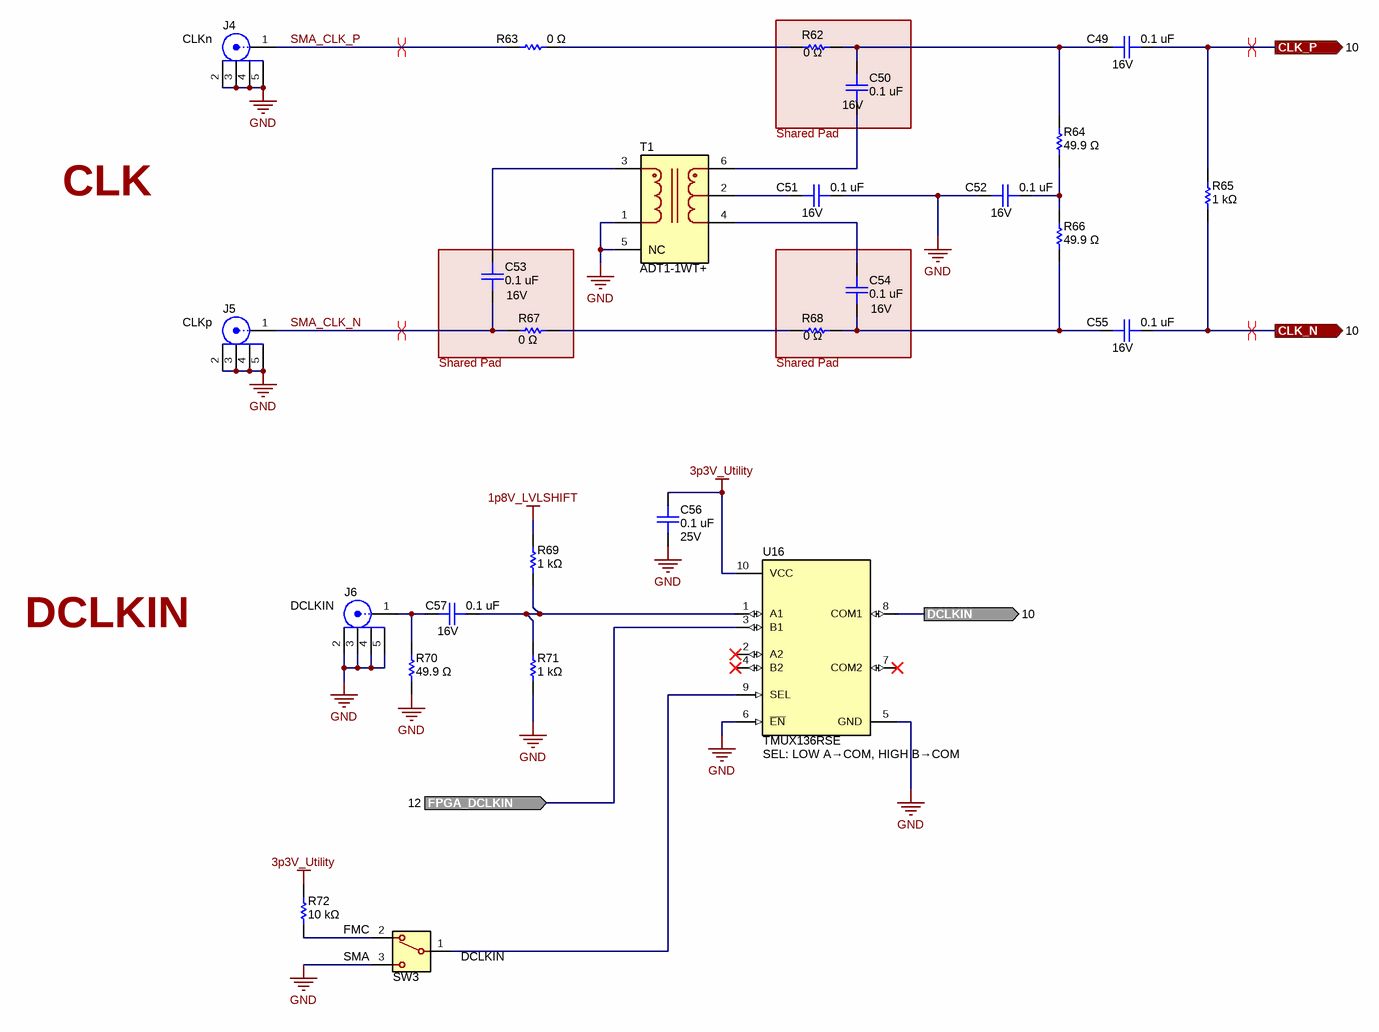
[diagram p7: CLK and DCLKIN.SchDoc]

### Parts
(Parts that share a designator on the sheet are numbered #1, #2 ... from top to bottom, then left to right.)
?#1  Shared Pad  (graphical)
?#2  Shared Pad  (graphical)
?#3  Shared Pad  (graphical)
C49  value 0.1 uF  Voltage - Rated: 16V  [0201_cap]  (hidden comment: GRM033Z71C104ME14D)
C50  value 0.1 uF  Voltage - Rated: 16V  [0201_cap]  (hidden comment: GRM033Z71C104ME14D)
C51  value 0.1 uF  Voltage - Rated: 16V  [0201_cap]  (hidden comment: GRM033Z71C104ME14D)
C52  value 0.1 uF  Voltage - Rated: 16V  [0201_cap]  (hidden comment: GRM033Z71C104ME14D)
C53  value 0.1 uF  Voltage - Rated: 16V  [0201_cap]  (hidden comment: GRM033Z71C104ME14D)
C54  value 0.1 uF  Voltage - Rated: 16V  [0201_cap]  (hidden comment: GRM033Z71C104ME14D)
C55  value 0.1 uF  Voltage - Rated: 16V  [0201_cap]  (hidden comment: GRM033Z71C104ME14D)
C56  value 0.1 uF  Voltage - Rated: 25V  [0402L_cap]  (hidden comment: GRT155R71E104KE01J)
C57  value 0.1 uF  Voltage - Rated: 16V  [0201_cap]  (hidden comment: GRM033Z71C104ME14D)
J4  Text1: CLKn  [FP-132134-15_CONN_SMA_JACK-MFG]  (hidden comment: 132134-15)
J5  Text1: CLKp  [FP-132134-15_CONN_SMA_JACK-MFG]  (hidden comment: 132134-15)
J6  Text1: DCLKIN  [FP-132134-15_CONN_SMA_JACK-MFG]  (hidden comment: 132134-15)
R62  value 0 Ω  [0201]  (hidden comment: ERJ-1GN0R00C)
R63  value 0 Ω  [0201]  (hidden comment: ERJ-1GN0R00C)
R64  value 49.9 Ω  [0201]  (hidden comment: ERJ-1GNF49R9C)
R65  value 1 kΩ  [0201]  (hidden comment: ERJ-1GNF1001C)
R66  value 49.9 Ω  [0201]  (hidden comment: ERJ-1GNF49R9C)
R67  value 0 Ω  [0201]  (hidden comment: ERJ-1GN0R00C)
R68  value 0 Ω  [0201]  (hidden comment: ERJ-1GN0R00C)
R69  value 1 kΩ  [0201]  (hidden comment: ERJ-1GNF1001C)
R70  value 49.9 Ω  [0201]  (hidden comment: ERJ-1GNF49R9C)
R71  value 1 kΩ  [0201]  (hidden comment: ERJ-1GNF1001C)
R72  value 10 kΩ  [0402L]  (hidden comment: ERA-2AEB103X)
SW3  Text1: DCLKIN  Text2: FMC  Text3: SMA  [450301014042]  (hidden comment: cmp00353)
T1  ADT1-1WT+  [CD542]
U16  TMUX136RSE  Text1: SEL: LOW A→COM, HIGH B→COM  [RSE0010A]

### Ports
CLK_N (out, see 10), CLK_P (out, see 10), DCLKIN (out, see 10), FPGA_DCLKIN (in, see 12)

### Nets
1p8V_LVLSHIFT: R69.2
3p3V_Utility: C56.2 R72.2 U16.10(VCC)
GND: C51.2 C52.1 C56.1 J4.2 J4.3 J4.4 J4.5 J5.2 J5.3 J5.4 J5.5 J6.2 J6.3 J6.4 J6.5 R70.1 R71.1 SW3.3 T1.1(PRIMARY) T1.5(NC) U16.5(GND) U16.6(~{EN})
CLK_N: C55.2 R65.1 ; port CLK_N
CLK_P: C49.2 R65.2 ; port CLK_P
DCLKIN: U16.8(COM1) ; port DCLKIN
FPGA_DCLKIN: U16.3(B1) ; port FPGA_DCLKIN
SMA_CLK_N: C53.2 J5.1 R67.1
SMA_CLK_P: J4.1 R63.1
NetC49_1: C49.1 C50.2 R62.2 R64.2
NetC50_1: C50.1 T1.6(SECONDARY_DOT)
NetC51_1: C51.1 T1.2(SECONDARY_CT)
NetC52_2: C52.2 R64.1 R66.2
NetC53_1: C53.1 T1.3(PRIMARY_DOT)
NetC54_1: C54.1 C55.1 R66.1 R68.2
NetC54_2: C54.2 T1.4(SECONDARY)
NetC57_1: C57.1 R69.1 R71.2 U16.1(A1)
NetC57_2: C57.2 J6.1 R70.2
NetR62_1: R62.1 R63.2
NetR67_2: R67.2 R68.1
NetR72_1: R72.1 SW3.2(COMM)
NetSW3_1: SW3.1 U16.9(SEL)

Not connected (* = marked no-connect by the designer): U16 2(A2)* 4(B2)* 7(COM2)*

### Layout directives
differential pair; net class DiffPairIN: CLK_N, CLK_P
differential pair: SMA_CLK_N, SMA_CLK_P

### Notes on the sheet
- CLK
- DCLKIN

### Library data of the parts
?#1-?#3 = Swizzle: Schematic notation to show that the pads of two components should be overlapped
C49-C55 C57 = capcc09270: CAP CER 0.1UF 16V X7R 0201; Manufacturer: Murata Electronics; CompType: Capacitor Ceramic; Tolerance: ±20%; SizeX_mm: 0.6; SizeY_mm: 0.3; SizeZ_mm: 0.33
C56 = capcc09401: as C17 on sheet Power LDO
J4-J6 = 132134-15: SMA Connector Jack, Female Socket 50Ohm Surface Mount, Through Hole Solder; Manufacturer: Amphenol RF; UniqueID: cmp00028; CompType: RF Connector
R62 R63 R67 R68 = RSMD020101699: as R35 on sheet USB Control FTDI
R64 R66 R70 = RSMD020100177: RES SMD 49.9 OHM 1% 1/20W 0201; Manufacturer: Panasonic Electronic Components; CompType: Resistor SMD; Power (Watts): 0.05W, 1/20W; Temperature Coefficient: ±200ppm/°C
R65 R69 R71 = RSMD020100143: RES SMD 1K OHM 1% 1/20W 0201; Manufacturer: Panasonic Electronic Components; CompType: Resistor SMD; Power (Watts): 0.05W, 1/20W; Temperature Coefficient: ±200ppm/°C
R72 = RSMD040200315: as R5 on sheet 12V Input, Efuse and 3p3V Utility
SW3 = cmp00353: as SW2 on sheet Comms LVL Shift and MUX
T1 = ADT1-1WT+: RF Transformer, 75 ohm, 1: 1, 0.4-800MHz, SMT; Manufacturer: Mini-Circuits; AEC Qualified: No; Return Loss: 9.75dB; Insertion Loss: 0.68-2.44dB; SizeZ_mm: 2.84mm
U16 = cmp00385: 1.4-pF on-state capacitance, 5-V, 2:1 (SPDT), 2-channel analog switch with powered-off protection; PartNumber: TMUX136RSER; Manufacturer: Texas Instruments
